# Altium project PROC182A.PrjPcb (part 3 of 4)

## Sheet PROC182A_MUX_CAN_FD.SchDoc: ANALOG MUX AND CAN FD_B
size 431 x 279 mm; Date: Not shown in title block; ApprovedBy: Not shown in title block; CheckedBy: Not shown in title block; Author: Not shown in title block; CompanyName: Not shown in title block; DrawnBy: Mistral; Engineer: Not shown in title block; Organization: Not shown in title block; Address1: Not shown in title block; Address2: Not shown in title block; Address3: Not shown in title block; Address4: Not shown in title block; DocumentNumber: 10; Revision: Use project parameter SCH_Rev; SheetNumber: 12; SheetTotal: 17; PageSetup: Record=PageOptions¦CenterHorizontal=True¦CenterVertical=True¦PrintScale=1.00¦XCorrection=1.00¦YCorrection=1.00¦PrintKind=0¦BorderSize=5000000¦LeftOffset=0¦BottomOffset=0¦Orientation=2¦PaperLength=1000¦PaperWidth=1000¦Scale=100¦PaperSource=15¦PrintQuality=600¦MediaType=1¦DitherType=10¦PaperKind=Letter¦PrintScaleMode=1
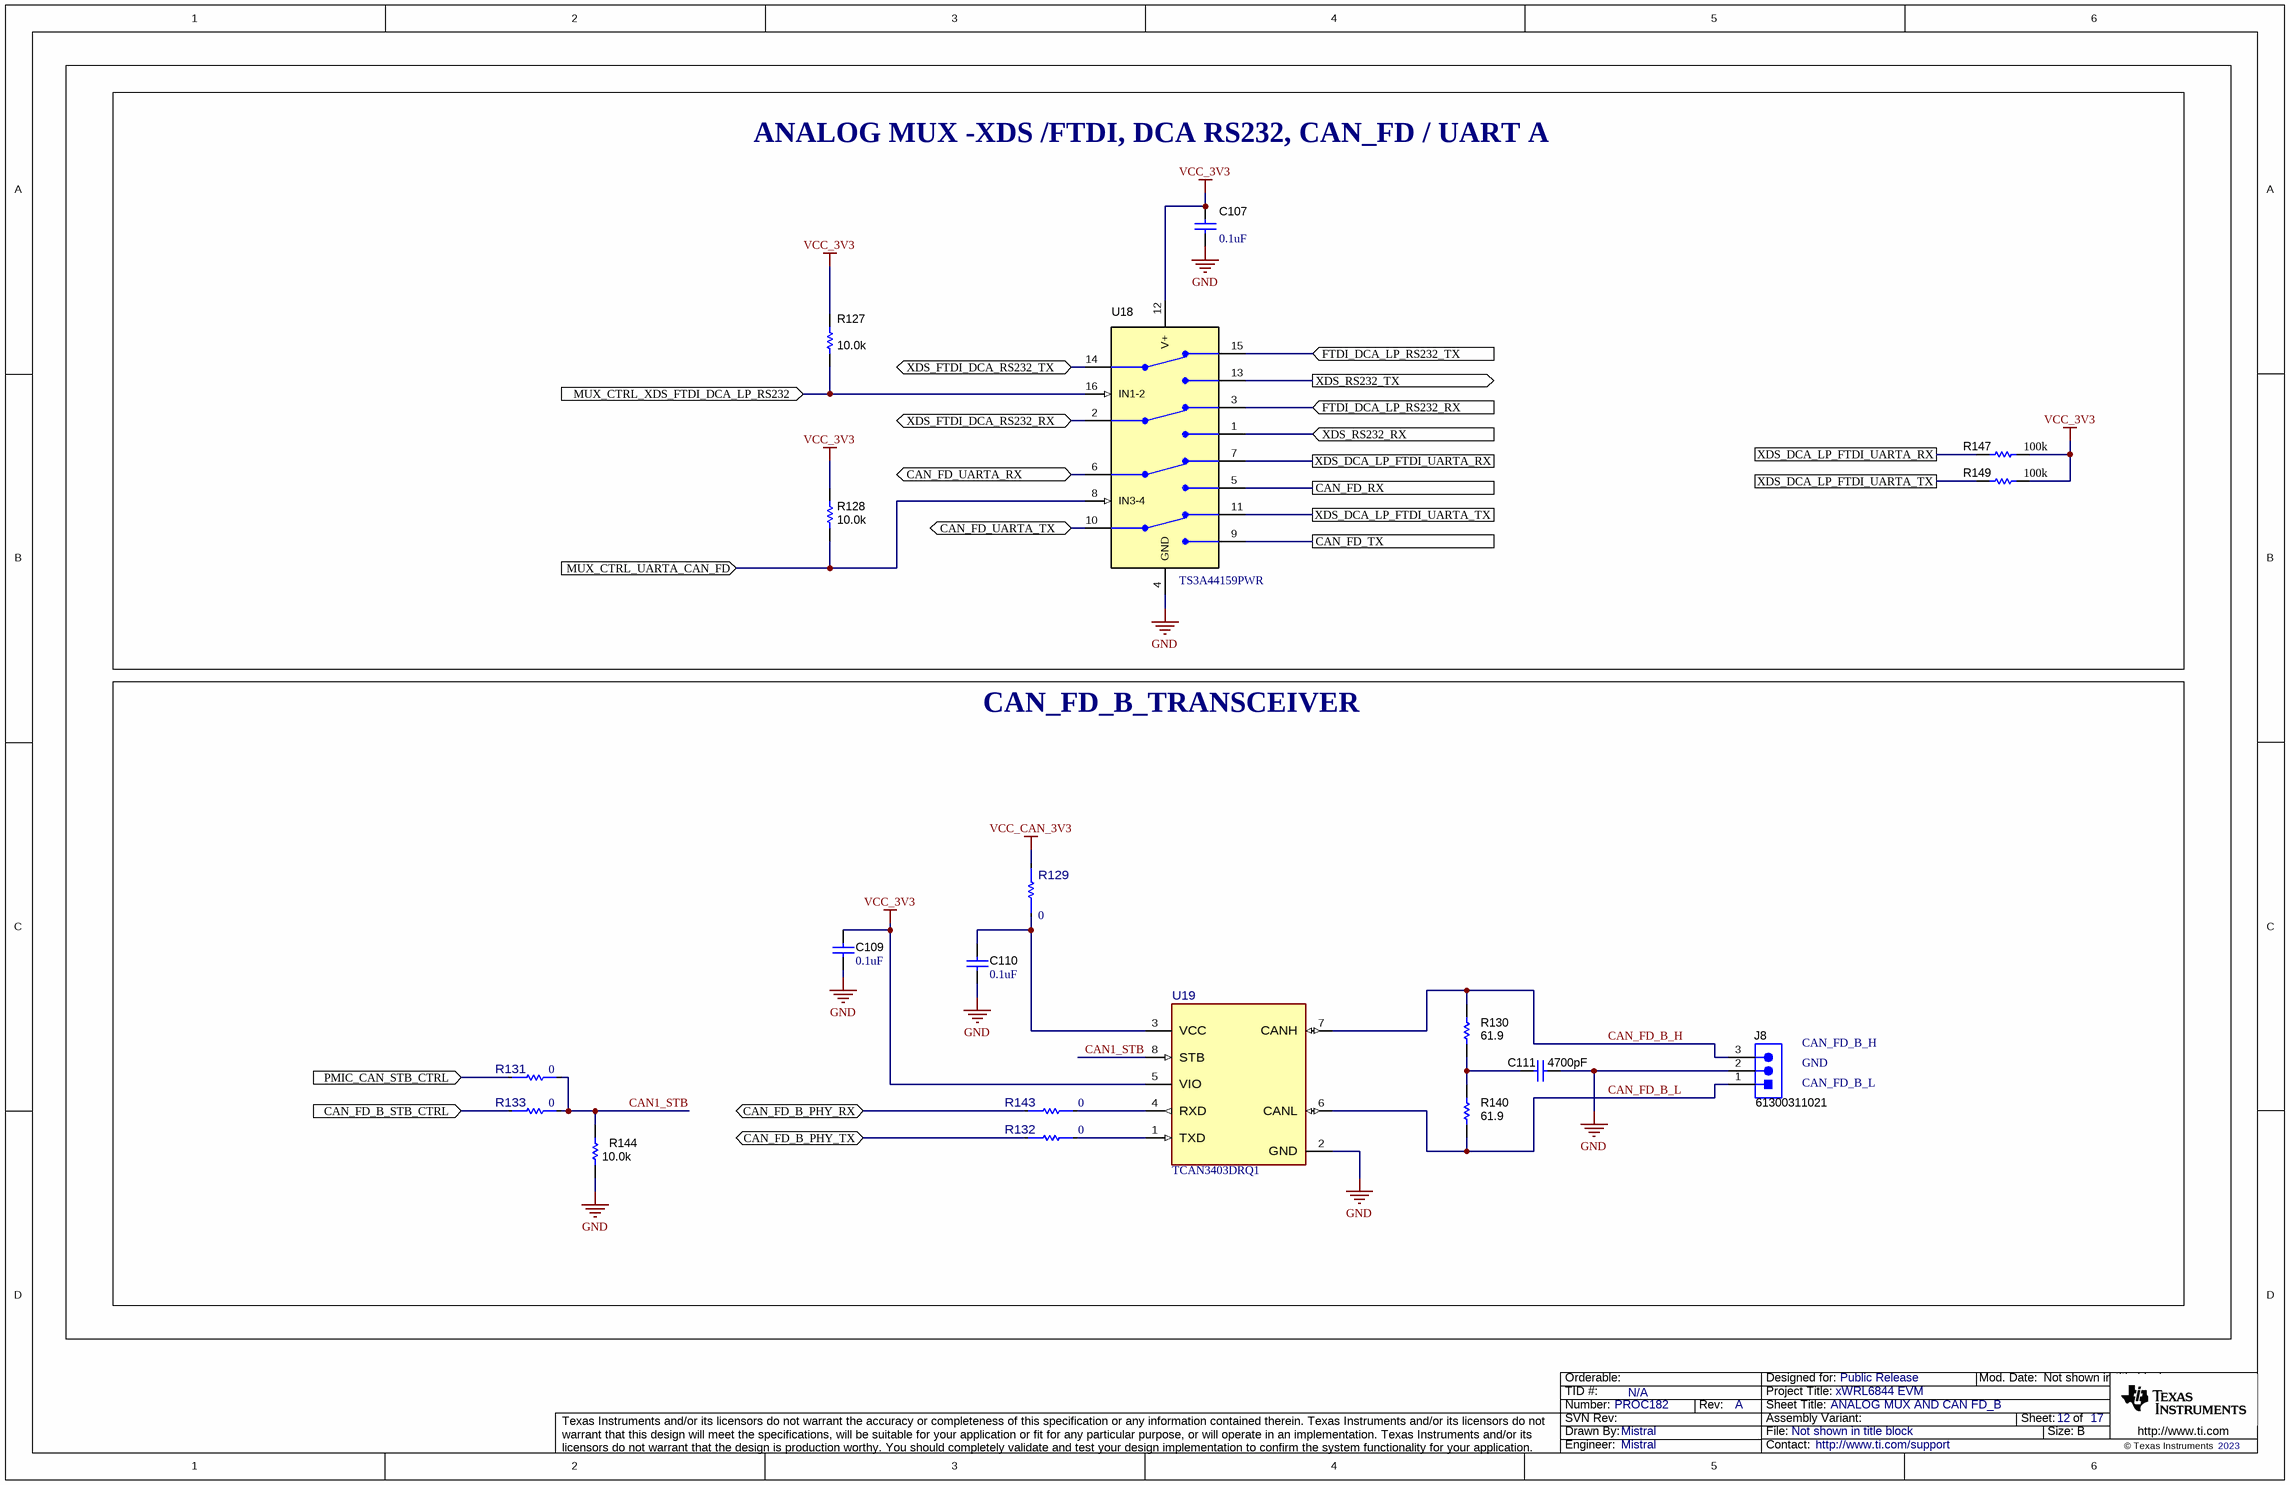
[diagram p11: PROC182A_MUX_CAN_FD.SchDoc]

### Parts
C107  ValueDisplayed: 0.1uF  [0402]  (hidden comment: GCM155R71H104KE02D)
C109  ValueDisplayed: 0.1uF  [0402]  (hidden comment: GCM155R71H104KE02D)
C110  ValueDisplayed: 0.1uF  [0402]  (hidden comment: GCM155R71H104KE02D)
C111  ValueDisplayed: 4700pF  [0402L]  (hidden comment: GCM155R71H472KA37D)
J8  61300311021  [Wurth_61300311021]
R127  ValueDisplayed: 10.0k  [0402L]  (hidden comment: CRCW040210K0FKED)
R128  ValueDisplayed: 10.0k  [0402L]  (hidden comment: CRCW040210K0FKED)
R129  value 0  [FP-ERJ-2GE0R00X_0402-MFG]  (hidden comment: ERJ-2GE0R00X)
R130  ValueDisplayed: 61.9  [0402L]  (hidden comment: CRCW040261R9FKED)
R131  value 0  [FP-ERJ-2GE0R00X_0402-MFG]  (hidden comment: ERJ-2GE0R00X)
R132  value 0  [FP-ERJ-2GE0R00X_0402-MFG]  (hidden comment: ERJ-2GE0R00X)
R133  value 0  [FP-ERJ-2GE0R00X_0402-MFG]  (hidden comment: ERJ-2GE0R00X)
R140  ValueDisplayed: 61.9  [0402L]  (hidden comment: CRCW040261R9FKED)
R143  value 0  [FP-ERJ-2GE0R00X_0402-MFG]  (hidden comment: ERJ-2GE0R00X)
R144  ValueDisplayed: 10.0k  [0402L]  (hidden comment: CRCW040210K0FKED)
R147  ValueDisplayed: 100k  [0402L]  (hidden comment: CRCW0402100KFKED)
R149  ValueDisplayed: 100k  [0402L]  (hidden comment: CRCW0402100KFKED)
U18  TS3A44159PWR  [PW0016A_N]
U19  TCAN3403DRQ1  [D0008B-MFG]

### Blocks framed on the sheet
ANALOG MUX -XDS /FTDI, DCA RS232, CAN_FD / UART A: C107 R127 R128 R147 R149 U18
CAN_FD_B_TRANSCEIVER: C109-C111 J8 R129-R133 R140 R143 R144 U19

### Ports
CAN_FD_B_PHY_RX (bidir), CAN_FD_B_PHY_TX (bidir), CAN_FD_B_STB_CTRL (in), CAN_FD_RX, CAN_FD_TX, CAN_FD_UARTA_RX (bidir), CAN_FD_UARTA_TX (bidir), FTDI_DCA_LP_RS232_RX (in), FTDI_DCA_LP_RS232_TX (in), MUX_CTRL_UARTA_CAN_FD (in), MUX_CTRL_XDS_FTDI_DCA_LP_RS232 (in), PMIC_CAN_STB_CTRL (in), XDS_DCA_LP_FTDI_UARTA_RX, XDS_DCA_LP_FTDI_UARTA_TX, XDS_FTDI_DCA_RS232_RX (bidir), XDS_FTDI_DCA_RS232_TX (bidir), XDS_RS232_RX (in), XDS_RS232_TX (out)

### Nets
GND: C107.2 C109.1 C110.1 C111.1 J8.2 R144.1 U18.4(GND) U19.2(GND)
VCC_3V3: C107.1 C109.2 R127.2 R128.2 R147.1 R149.1 U18.12(V+) U19.5(VIO)
VCC_CAN_3V3: R129.2
CAN1_STB: R131.2 R133.2 R144.2 U19.8(STB)
CAN_FD_B_H: J8.3 R130.2 U19.7(CANH)
CAN_FD_B_L: J8.1 R140.1 U19.6(CANL)
CAN_FD_B_PHY_RX: R143.1 ; port CAN_FD_B_PHY_RX
CAN_FD_B_PHY_TX: R132.1 ; port CAN_FD_B_PHY_TX
CAN_FD_B_STB_CTRL: R133.1 ; port CAN_FD_B_STB_CTRL
CAN_FD_RX: U18.5(NO3) ; port CAN_FD_RX
CAN_FD_TX: U18.9(NO4) ; port CAN_FD_TX
CAN_FD_UARTA_RX: U18.6(COM3) ; port CAN_FD_UARTA_RX
CAN_FD_UARTA_TX: U18.10(COM4) ; port CAN_FD_UARTA_TX
FTDI_DCA_LP_RS232_RX: U18.3(NC2) ; port FTDI_DCA_LP_RS232_RX
FTDI_DCA_LP_RS232_TX: U18.15(NC1) ; port FTDI_DCA_LP_RS232_TX
MUX_CTRL_UARTA_CAN_FD: R128.1 U18.8(IN3-4) ; port MUX_CTRL_UARTA_CAN_FD
MUX_CTRL_XDS_FTDI_DCA_LP_RS232: R127.1 U18.16(IN1-2) ; port MUX_CTRL_XDS_FTDI_DCA_LP_RS232
PMIC_CAN_STB_CTRL: R131.1 ; port PMIC_CAN_STB_CTRL
XDS_DCA_LP_FTDI_UARTA_RX: R147.2 U18.7(NC3) ; port XDS_DCA_LP_FTDI_UARTA_RX
XDS_DCA_LP_FTDI_UARTA_TX: R149.2 U18.11(NC4) ; port XDS_DCA_LP_FTDI_UARTA_TX
XDS_FTDI_DCA_RS232_RX: U18.2(COM2) ; port XDS_FTDI_DCA_RS232_RX
XDS_FTDI_DCA_RS232_TX: U18.14(COM1) ; port XDS_FTDI_DCA_RS232_TX
XDS_RS232_RX: U18.1(NO2) ; port XDS_RS232_RX
XDS_RS232_TX: U18.13(NO1) ; port XDS_RS232_TX
NetC110_2: C110.2 R129.1 U19.3(VCC)
NetC111_2: C111.2 R130.1 R140.2
NetR132_2: R132.2 U19.1(TXD)
NetR143_2: R143.2 U19.4(RXD)

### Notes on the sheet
- (near J8) CAN_FD_B_H
- (near J8) GND
- (near J8) CAN_FD_B_L

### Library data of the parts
C107 C109 C110 = CMP-0006356-2: CAP, CERM, 0.1 uF, 50 V, +/- 10%, X7R, AEC-Q200 Grade 1, 0402; Manufacturer: MuRata; TaMin_C: -55°C; Polarized: N; SizeAreaWB_mm2: 3; U/M: EA; Value: 0.1uF; TaMax_C: 125°C; SizeZ_mm: 0.6; SizeX_mm: 1; SizeY_mm: 0.5; Value2: 50V; AEC Qualified: Y; Cap_F: 100nF; AEC Category: Q200; Value1: Unknown
C111 = CMP-0006361-2: CAP, CERM, 4700 pF, 50 V, +/- 10%, X7R, AEC-Q200 Grade 1, 0402; Manufacturer: MuRata; TaMin_C: -55°C; Polarized: N; SizeAreaWB_mm2: 3; Value1: Unknown; U/M: EA; Value: 4700pF; TaMax_C: 125°C; SizeZ_mm: 0.6; SizeX_mm: 1; SizeY_mm: 0.5; Cap_Case: 0402; Value2: 50V; AEC Qualified: Y; Cap_F: 4.7nF; AEC Category: Q200
J8 = CMP-0054795-1: Header, 2.54 mm, 3x1, Gold, R/A, TH; Manufacturer: Wurth Elektronik; CNHeader: TRUE; Shrouded: N; Gender: Male; Row_Count: 1; Pitch_mm: 2.54; CT: FALSE
R127 R128 R144 = CMP-0025958-3: RES, 10.0 k, 1%, 0.063 W, AEC-Q200 Grade 0, 0402; Manufacturer: Vishay-Dale; Power_W: 63mW; TempCo: 100 ppm/C; Value_Code: 10k0; Value: 10.0k; EIA_Code: E96; Res_ohm: 10k; SizeX_mm: 1; SizeY_mm: 0.5; SizeZ_mm: 0.6; Value2: 0.063W; AEC Qualified: Y; VDC_V: 50V; AEC Category: Q200; AEC Grade: 0
R129 R131-R133 R143 = CMP-0002710-1: 0 Ohms Jumper Chip Resistor 0402 (1005 Metric) Automotive AEC-Q200 Thick Film; Manufacturer: Panasonic; SizeZ_mm: 0.4mm; AEC Qualified: Yes; AEC Grade: Grade 0; Power: 100mW
R130 R140 = CMP-0026491-2: RES, 61.9, 1%, 0.063 W, AEC-Q200 Grade 0, 0402; Manufacturer: Vishay-Dale; Power_W: 63mW; TempCo: 100 ppm/C; Value_Code: 61R9; Value: 61.9; EIA_Code: E96; SizeX_mm: 1; SizeY_mm: 0.5; SizeZ_mm: 0.6; Value2: 0.063W; AEC Qualified: Y; VDC_V: 50V; AEC Category: Q200; AEC Grade: 0
R147 R149 = CMP-0025950-3: RES, 100 k, 1%, 0.063 W, AEC-Q200 Grade 0, 0402; Manufacturer: Vishay-Dale; Power_W: 63mW; TempCo: 100 ppm/C; Value: 100k; EIA_Code: E96; SizeX_mm: 1; SizeY_mm: 0.5; SizeZ_mm: 0.6; Value2: 0.063W; AEC Qualified: Y; VDC_V: 50V; AEC Category: Q200; AEC Grade: 0
U18 = CMP-0067412-1: 0.45-Ohm Quad SPDT Analog Switch Quad-Channel 2:1 Multiplexer/Demultiplexer with Two Controls, PW0016A (TSSOP-16); Alternate Manufacturer: Texas Instruments; SizeAreaWB_mm2: 58.8; U/M: EA; SizeZ_mm: 1.2; SizeX_mm: 6.4; SizeY_mm: 5.0; SizeArea_mm2: 32.0; CompType: IC
U19 = CMP-0121020-1: Dual, Simultaneous-Sampling, 16-Bit, 5 MSPS SAR ADCs; Manufacturer: Texas Instruments; SizeZ_mm: 1.75mm; AEC Qualified: Yes; AEC Grade: Grade 1; Interface: CAN; Max Supply Voltage: 3.6V; Min Supply Voltage: 1.7V; Standoff Height: 0.11mm

## Sheet PROC182A_CAN_LIN_PHY_Interface.SchDoc: CAN_LIN_PHY_INTERFACE
size 431 x 279 mm; Date: Not shown in title block; ApprovedBy: Not shown in title block; CheckedBy: Not shown in title block; Author: Not shown in title block; CompanyName: Not shown in title block; DrawnBy: Mistral; Engineer: Not shown in title block; Organization: Not shown in title block; Address1: Not shown in title block; Address2: Not shown in title block; Address3: Not shown in title block; Address4: Not shown in title block; DocumentNumber: 13; Revision: Use project parameter SCH_Rev; SheetNumber: 13; SheetTotal: 17; PageSetup: Record=PageOptions¦CenterHorizontal=True¦CenterVertical=True¦PrintScale=1.00¦XCorrection=1.00¦YCorrection=1.00¦PrintKind=0¦BorderSize=5000000¦LeftOffset=0¦BottomOffset=0¦Orientation=2¦PaperLength=1000¦PaperWidth=1000¦Scale=100¦PaperSource=15¦PrintQuality=600¦MediaType=1¦DitherType=10¦PaperKind=Letter¦PrintScaleMode=1
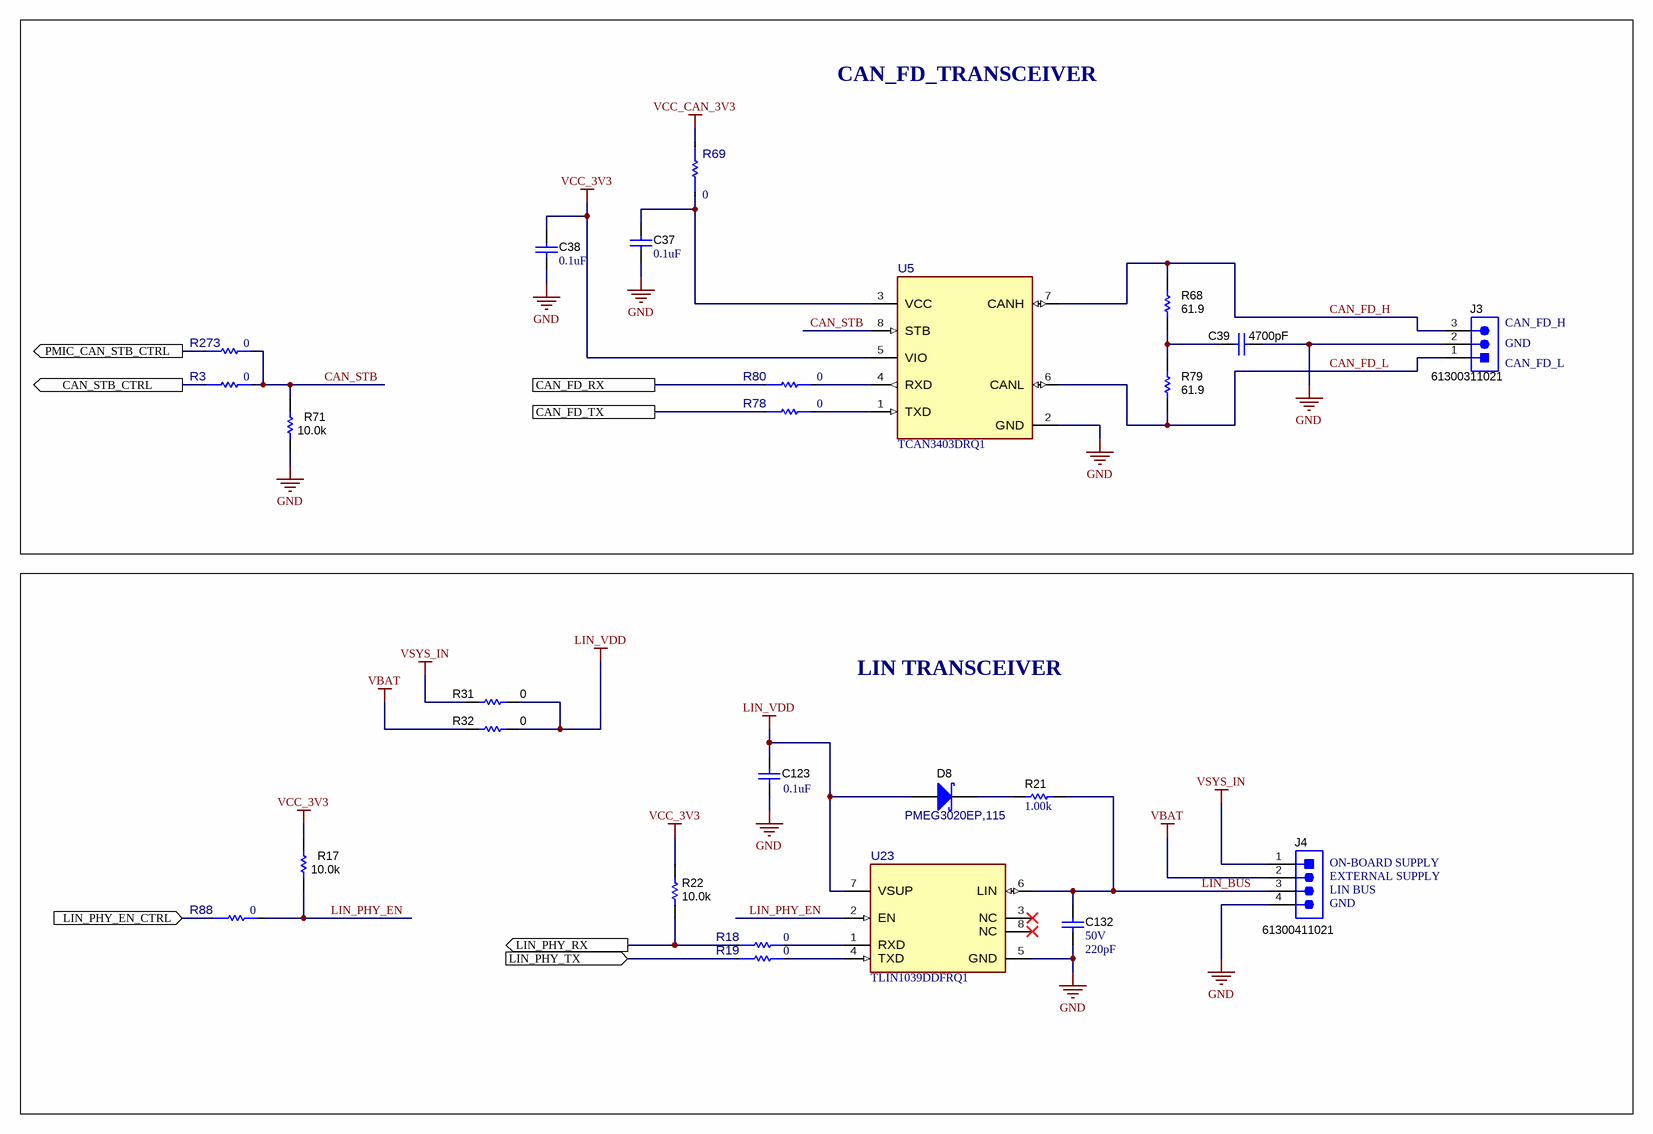
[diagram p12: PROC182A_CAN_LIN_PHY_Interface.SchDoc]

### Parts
C37  ValueDisplayed: 0.1uF  [0402]  (hidden comment: GCM155R71H104KE02D)
C38  ValueDisplayed: 0.1uF  [0402]  (hidden comment: GCM155R71H104KE02D)
C39  ValueDisplayed: 4700pF  [0402L]  (hidden comment: GCM155R71H472KA37D)
C123  ValueDisplayed: 0.1uF  [0402]  (hidden comment: GCM155R71H104KE02D)
C132  VDC_V: 50V  ValueDisplayed: 220pF  [0402]  (hidden comment: 885012005063)
D8  PMEG3020EP,115  [SOD-128]
J3  61300311021  [Wurth_61300311021]
J4  61300411021  [Wurth_61300411021]
R3  value 0  [FP-ERJ-2GE0R00X_0402-MFG]  (hidden comment: ERJ-2GE0R00X)
R17  ValueDisplayed: 10.0k  [0402L]  (hidden comment: CRCW040210K0FKED)
R18  value 0  [FP-ERJ-2GE0R00X_0402-MFG]  (hidden comment: ERJ-2GE0R00X)
R19  value 0  [FP-ERJ-2GE0R00X_0402-MFG]  (hidden comment: ERJ-2GE0R00X)
R21  ValueDisplayed: 1.00k  [0402]  (hidden comment: ERJ-2RKF1001X)
R22  ValueDisplayed: 10.0k  [0402L]  (hidden comment: CRCW040210K0FKED)
R31  ValueDisplayed: 0  [0603]  (hidden comment: MCT06030Z0000ZP500)
R32  ValueDisplayed: 0  [0603]  (hidden comment: MCT06030Z0000ZP500)
R68  ValueDisplayed: 61.9  [0402L]  (hidden comment: CRCW040261R9FKED)
R69  value 0  [FP-ERJ-2GE0R00X_0402-MFG]  (hidden comment: ERJ-2GE0R00X)
R71  ValueDisplayed: 10.0k  [0402L]  (hidden comment: CRCW040210K0FKED)
R78  value 0  [FP-ERJ-2GE0R00X_0402-MFG]  (hidden comment: ERJ-2GE0R00X)
R79  ValueDisplayed: 61.9  [0402L]  (hidden comment: CRCW040261R9FKED)
R80  value 0  [FP-ERJ-2GE0R00X_0402-MFG]  (hidden comment: ERJ-2GE0R00X)
R88  value 0  [FP-ERJ-2GE0R00X_0402-MFG]  (hidden comment: ERJ-2GE0R00X)
R273  value 0  [FP-ERJ-2GE0R00X_0402-MFG]  (hidden comment: ERJ-2GE0R00X)
U5  TCAN3403DRQ1  [D0008B-MFG]
U23  TLIN1039DDFRQ1  [DDF0008A-MFG]

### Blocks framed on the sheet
CAN_FD_TRANSCEIVER: C37-C39 J3 R3 R68 R69 R71 R78-R80 R273 U5
LIN TRANSCEIVER: C123 C132 D8 J4 R17-R19 R21 R22 R31 R32 R88 U23

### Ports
CAN_FD_RX, CAN_FD_TX, CAN_STB_CTRL (out), LIN_PHY_EN_CTRL (in), LIN_PHY_RX (out), LIN_PHY_TX (in), PMIC_CAN_STB_CTRL (out)

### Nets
GND: C37.1 C38.1 C39.1 C123.2 C132.2 J3.2 J4.4 R71.1 U5.2(GND) U23.5(GND)
LIN_VDD: C123.1 D8.2(A) R31.2 R32.2 U23.7(VSUP)
VBAT: J4.2 R32.1
VCC_3V3: C38.2 R17.2 R22.2 U5.5(VIO)
VCC_CAN_3V3: R69.2
VSYS_IN: J4.1 R31.1
CAN_FD_H: J3.3 R68.2 U5.7(CANH)
CAN_FD_L: J3.1 R79.1 U5.6(CANL)
CAN_FD_RX: R80.1 ; port CAN_FD_RX
CAN_FD_TX: R78.1 ; port CAN_FD_TX
CAN_STB: R3.2 R71.2 R273.2 U5.8(STB)
CAN_STB_CTRL: R3.1 ; port CAN_STB_CTRL
LIN_BUS: C132.1 J4.3 R21.1 U23.6(LIN)
LIN_PHY_EN: R17.1 R88.2 U23.2(EN)
LIN_PHY_EN_CTRL: R88.1 ; port LIN_PHY_EN_CTRL
LIN_PHY_RX: R18.1 R22.1 ; port LIN_PHY_RX
LIN_PHY_TX: R19.1 ; port LIN_PHY_TX
PMIC_CAN_STB_CTRL: R273.1 ; port PMIC_CAN_STB_CTRL
NetC37_2: C37.2 R69.1 U5.3(VCC)
NetC39_2: C39.2 R68.1 R79.2
NetD8_1: D8.1(K) R21.2
NetR18_2: R18.2 U23.1(RXD)
NetR19_2: R19.2 U23.4(TXD)
NetR78_2: R78.2 U5.1(TXD)
NetR80_2: R80.2 U5.4(RXD)

Not connected (* = marked no-connect by the designer): U23 3(NC)* 8(NC)*

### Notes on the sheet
- (near J3) CAN_FD_H
- (near J3) GND
- (near J3) CAN_FD_L
- (near J4) ON-BOARD SUPPLY
- (near J4) EXTERNAL SUPPLY
- (near J4) LIN BUS
- (near J4) GND

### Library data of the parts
C37 C38 = CMP-0006356-2: as C107 on sheet PROC182A_MUX_CAN_FD
C39 = CMP-0006361-2: as C111 on sheet PROC182A_MUX_CAN_FD
C123 = CMP-0006356-2: CAP, CERM, 0.1 uF, 50 V, +/- 10%, X7R, AEC-Q200 Grade 1, 0402; Manufacturer: MuRata; TaMin_C: -55°C; Polarized: N; SizeAreaWB_mm2: 3; Value1: Unknown; U/M: EA; Value: 0.1uF; TaMax_C: 125°C; SizeZ_mm: 0.6; SizeX_mm: 1; SizeY_mm: 0.5; Value2: 50V; AEC Qualified: Y; Cap_F: 100nF; AEC Category: Q200
C132 = CMP-0006218-2: CAP, CERM, 220 pF, 50 V, +/- 5%, C0G/NP0, 0402; Manufacturer: Wurth Elektronik; TaMin_C: -55°C; Polarized: N; SizeAreaWB_mm2: 3; Value1: Unknown; U/M: EA; Value: 220pF; TaMax_C: 125°C; SizeZ_mm: 0.6; SizeX_mm: 1; SizeY_mm: 0.5; AEC Category: Q200
D8 = CMP-0078758-2: Diode, Schottky, 30 V, 2 A, AEC-Q101, SOD-128; Manufacturer: Nexperia; Value2: 0.36V; SizeAreaWB_mm2: 19.6; Io_A: 2A; Value: 30V; AEC Qualified: Y; TJmax_C: 150°C; SizeX_mm: 4.6; AEC Category: Q101; SizeY_mm: 2.5; SizeArea_mm2: 11.5; Vf_V: 3.6dV; SizeZ_mm: 1.1
J3 = CMP-0054795-1: as J8 on sheet PROC182A_MUX_CAN_FD
J4 = CMP-0054797-1: Header, 2.54 mm, 4x1, Gold, R/A, TH; Manufacturer: Wurth Elektronik; CNHeader: TRUE; Shrouded: N; Gender: Male; Row_Count: 1; Pitch_mm: 2.54; CT: FALSE
R3 R18 R19 R69 R78 R80 R88 R273 = CMP-0002710-1: as R129 on sheet PROC182A_MUX_CAN_FD
R17 R22 R71 = CMP-0025958-3: as R127 on sheet PROC182A_MUX_CAN_FD
R21 = CMP-0026657-1: RES, 1.00 k, 1%, 0.1 W, 0402; Manufacturer: Panasonic; Power_W: 100mW; TempCo: 100 ppm/C; Value_Code: 1k00; Value: 1.00k; EIA_Code: E96; Res_ohm: 1k; SizeX_mm: 1; SizeY_mm: 0.5; SizeZ_mm: 0.6; Value2: 0.1W; VDC_V: 50V; AEC Category: Q200; U/M: EA
R31 R32 = CMP-0025884-3: RES, 0, 5%, 0.125 W, 0603; Manufacturer: Vishay/Beyschlag; Power_W: 125mW; TempCo: ppm/C; Value_Code: 0000; U/M: EA; Value: 0; EIA_Code: E24; SizeX_mm: 1.6; SizeY_mm: 0.8; SizeZ_mm: 1; Value2: 0.125W; SizeArea_mm2: 1.28; CompType: Resistor; AEC Qualified: N; AEC Category: Q200; INSTALATION: DNP
R68 R79 = CMP-0026491-2: as R130 on sheet PROC182A_MUX_CAN_FD
U5 = CMP-0121020-1: as U19 on sheet PROC182A_MUX_CAN_FD
U23 = CMP-0090433-1: Local Interconnect Network (LIN) Transceiver with Dominant State Timeout; Manufacturer: Texas Instruments; Max Supply Voltage: 36V; SizeZ_mm: 1.1mm; Min Supply Voltage: 4.5V; Standoff Height: 0mm; Nominal Supply Current: 0.3-1.2mA; AEC Grade: Grade 0; TJmax_C: +150°C; Interface: UART,LIN,SCI; AEC Qualified: Yes

## Sheet PROC182A_FTDI.SchDoc: FTDI_USB to SPI/12C/UART_Converter
size 431 x 279 mm; Date: Not shown in title block; ApprovedBy: Not shown in title block; CheckedBy: Not shown in title block; Author: Not shown in title block; CompanyName: Not shown in title block; DrawnBy: Mistral; Engineer: Not shown in title block; Organization: Not shown in title block; Address1: Not shown in title block; Address2: Not shown in title block; Address3: Not shown in title block; Address4: Not shown in title block; DocumentNumber: 14; Revision: Use project parameter SCH_Rev; SheetNumber: 14; SheetTotal: 17; PageSetup: Record=PageOptions¦CenterHorizontal=True¦CenterVertical=True¦PrintScale=1.00¦XCorrection=1.00¦YCorrection=1.00¦PrintKind=0¦BorderSize=5000000¦LeftOffset=0¦BottomOffset=0¦Orientation=2¦PaperLength=1000¦PaperWidth=1000¦Scale=100¦PaperSource=15¦PrintQuality=600¦MediaType=1¦DitherType=10¦PaperKind=Letter¦PrintScaleMode=1
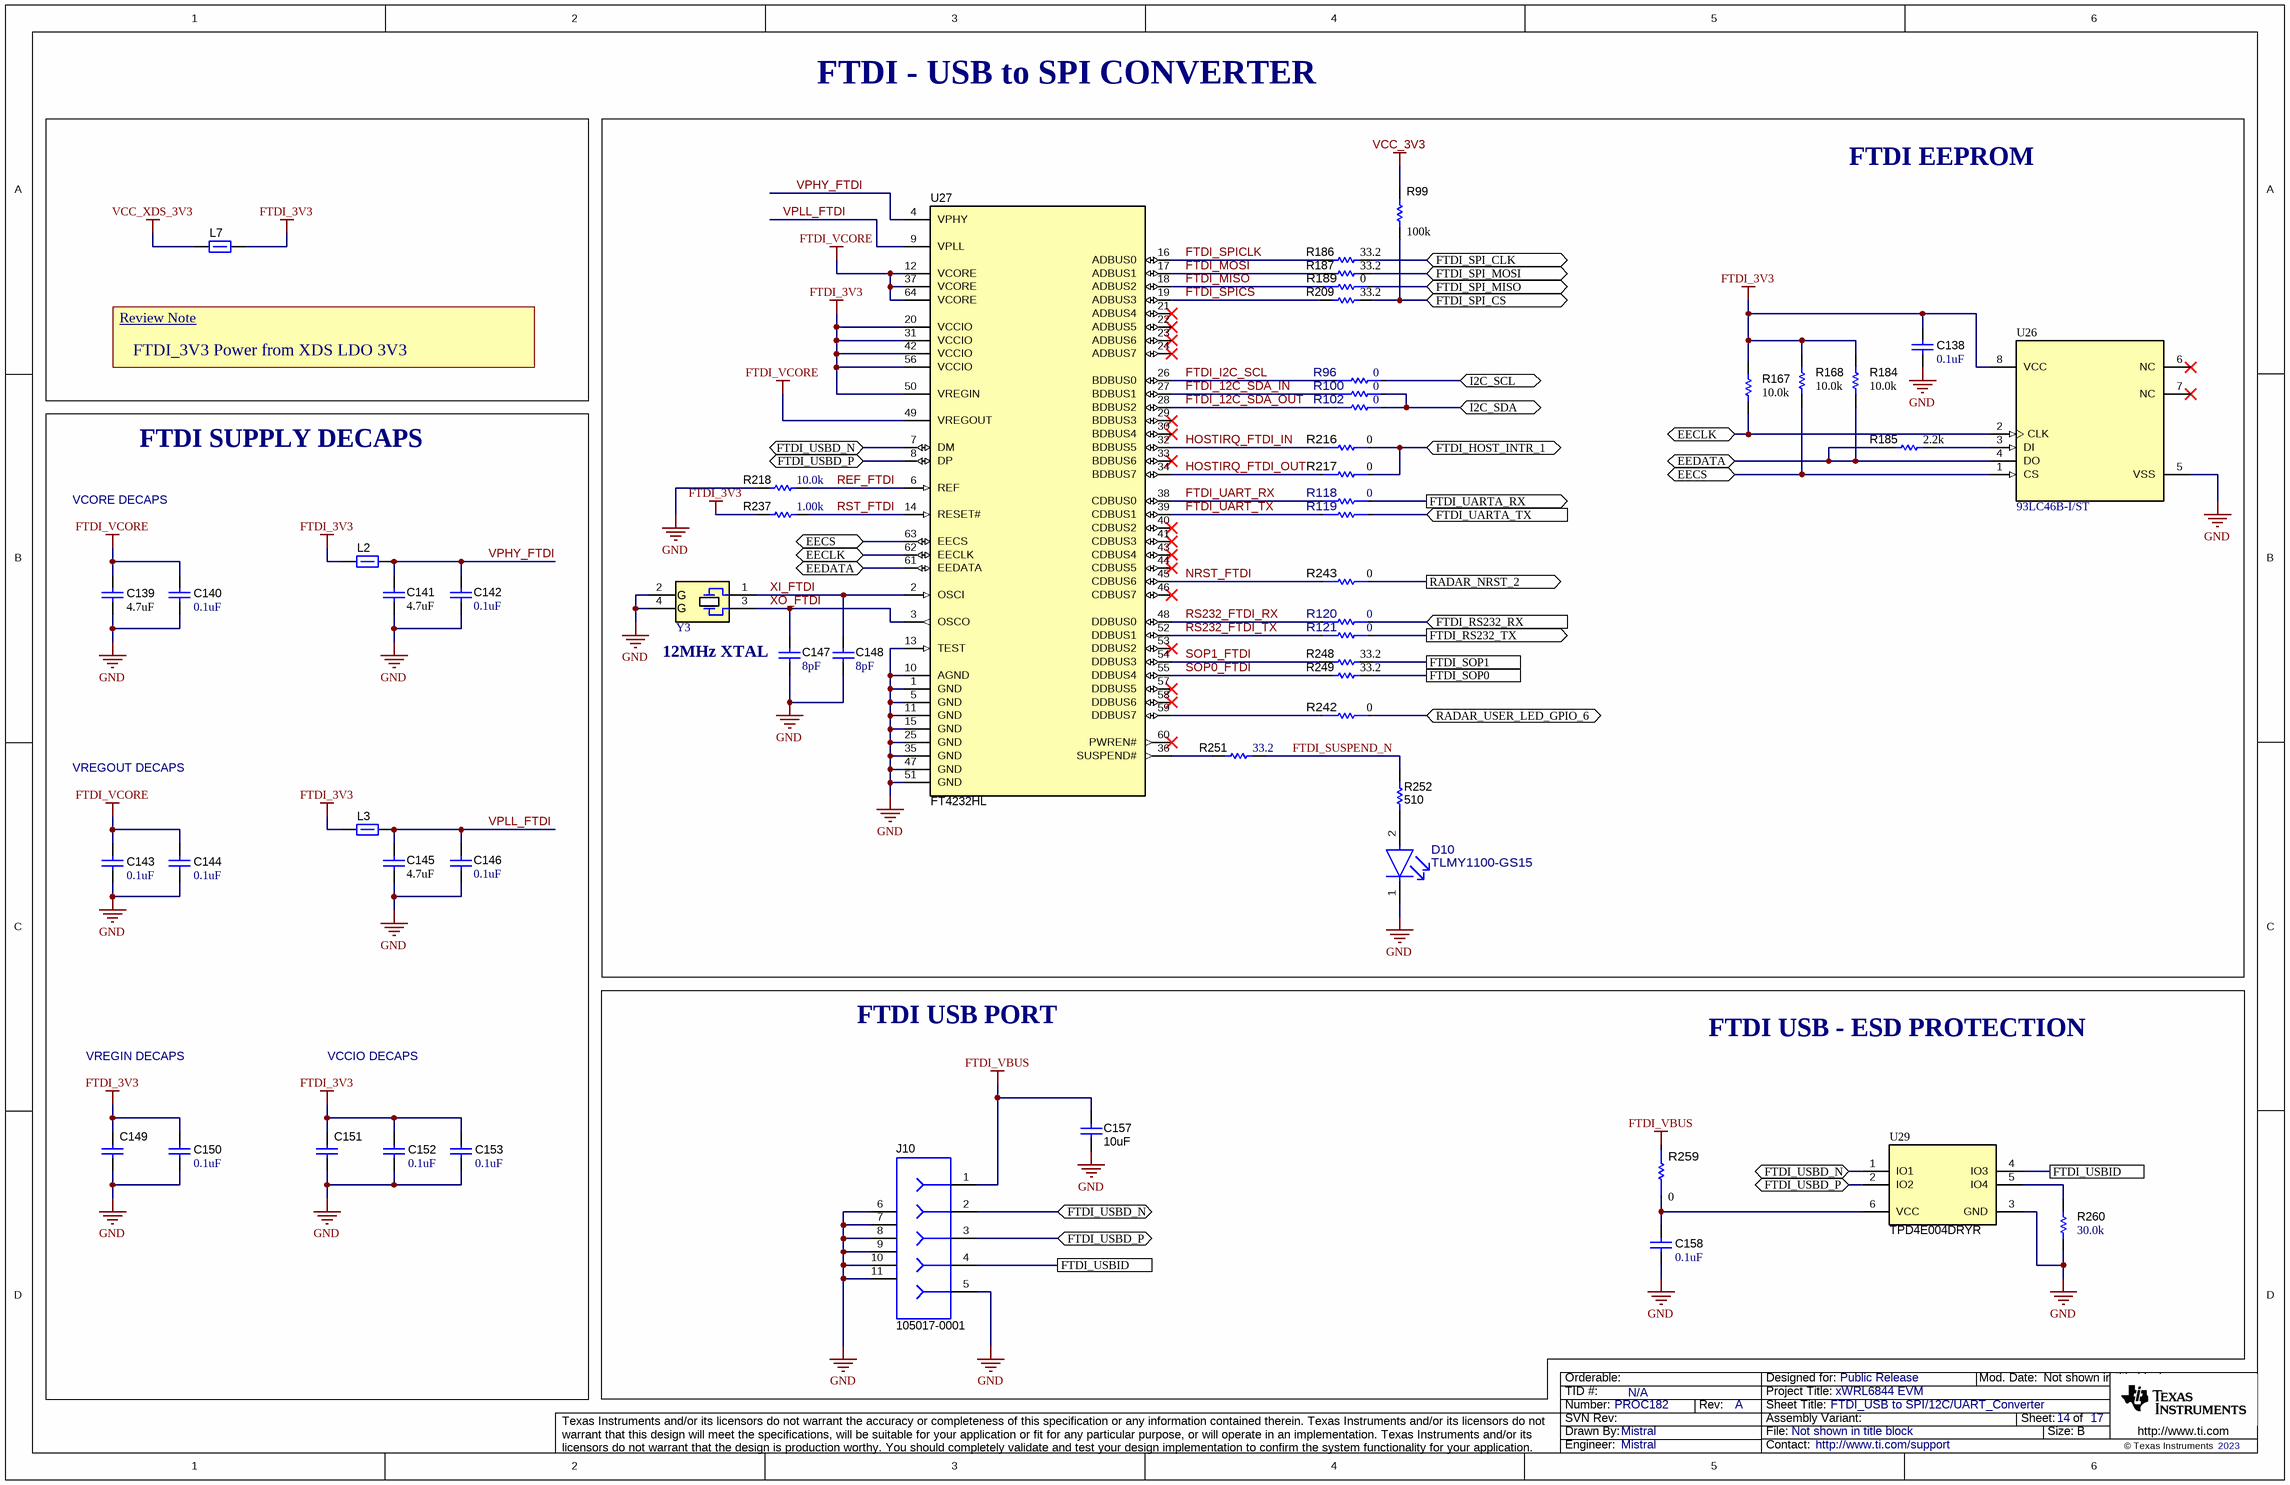
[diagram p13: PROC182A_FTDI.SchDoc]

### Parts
C138  ValueDisplayed: 0.1uF  [0402]  (hidden comment: GCM155R71H104KE02D)
C139  ValueDisplayed: 4.7uF  [0603L]  (hidden comment: C1608X7S1A475K080AC)
C140  ValueDisplayed: 0.1uF  [0402]  (hidden comment: GCM155R71H104KE02D)
C141  ValueDisplayed: 4.7uF  [0603L]  (hidden comment: C1608X7S1A475K080AC)
C142  ValueDisplayed: 0.1uF  [0402]  (hidden comment: GCM155R71H104KE02D)
C143  ValueDisplayed: 0.1uF  [0402]  (hidden comment: GCM155R71H104KE02D)
C144  ValueDisplayed: 0.1uF  [0402]  (hidden comment: GCM155R71H104KE02D)
C145  ValueDisplayed: 4.7uF  [0603L]  (hidden comment: C1608X7S1A475K080AC)
C146  ValueDisplayed: 0.1uF  [0402]  (hidden comment: GCM155R71H104KE02D)
C147  Cap_F: 8pF  [0402L]  (hidden comment: GCM1555C1H8R0DA16D)
C148  Cap_F: 8pF  [0402L]  (hidden comment: GCM1555C1H8R0DA16D)
C149  CL10B105KA8NNNC  [0603]  (value not drawn)
C150  ValueDisplayed: 0.1uF  [0402]  (hidden comment: GCM155R71H104KE02D)
C151  CL10B105KA8NNNC  [0603]  (value not drawn)
C152  ValueDisplayed: 0.1uF  [0402]  (hidden comment: GCM155R71H104KE02D)
C153  ValueDisplayed: 0.1uF  [0402]  (hidden comment: GCM155R71H104KE02D)
C157  ValueDisplayed: 10uF  [0603S]  (hidden comment: GRT188R61A106KE13D)
C158  ValueDisplayed: 0.1uF  [0402]  (hidden comment: GCM155R71H104KE02D)
D10  TLMY1100-GS15  [FP-TLMY1100-GS15_0603-MFG]
J10  105017-0001  [CONN_105017-0001]
L2  BLM15HG601SN1D  [0402L]  (value not drawn)
L3  BLM15HG601SN1D  [0402L]  (value not drawn)
L7  BLM15HG601SN1D  [0402L]  (value not drawn)
R96  value 0  [FP-ERJ-2GE0R00X_0402-MFG]  (hidden comment: ERJ-2GE0R00X)
R99  ValueDisplayed: 100k  [0402]  (hidden comment: CRCW0402100KFKED)
R100  value 0  [FP-ERJ-2GE0R00X_0402-MFG]  (hidden comment: ERJ-2GE0R00X)
R102  value 0  [FP-ERJ-2GE0R00X_0402-MFG]  (hidden comment: ERJ-2GE0R00X)
R118  value 0  [FP-ERJ-2GE0R00X_0402-MFG]  (hidden comment: ERJ-2GE0R00X)
R119  ERJ-2GE0R00X  [FP-ERJ-2GE0R00X_0402-MFG]  (value not drawn)
R120  value 0  [FP-ERJ-2GE0R00X_0402-MFG]  (hidden comment: ERJ-2GE0R00X)
R121  value 0  [FP-ERJ-2GE0R00X_0402-MFG]  (hidden comment: ERJ-2GE0R00X)
R167  ValueDisplayed: 10.0k  [0402L]  (hidden comment: CRCW040210K0FKED)
R168  ValueDisplayed: 10.0k  [0402L]  (hidden comment: CRCW040210K0FKED)
R184  ValueDisplayed: 10.0k  [0402L]  (hidden comment: CRCW040210K0FKED)
R185  ValueDisplayed: 2.2k  [0402L]  (hidden comment: CRCW04022K20JNED)
R186  ValueDisplayed: 33.2  [0402]  (hidden comment: CRCW040233R2FKED)
R187  ValueDisplayed: 33.2  [0402]  (hidden comment: CRCW040233R2FKED)
R189  value 0  [FP-ERJ-2GE0R00X_0402-MFG]  (hidden comment: ERJ-2GE0R00X)
R209  ValueDisplayed: 33.2  [0402]  (hidden comment: CRCW040233R2FKED)
R216  value 0  [FP-ERJ-2GE0R00X_0402-MFG]  (hidden comment: ERJ-2GE0R00X)
R217  value 0  [FP-ERJ-2GE0R00X_0402-MFG]  (hidden comment: ERJ-2GE0R00X)
R218  ValueDisplayed: 10.0k  [0402L]  (hidden comment: CRCW040210K0FKED)
R237  ValueDisplayed: 1.00k  [0402]  (hidden comment: ERJ-2RKF1001X)
R242  value 0  [FP-ERJ-2GE0R00X_0402-MFG]  (hidden comment: ERJ-2GE0R00X)
R243  value 0  [FP-ERJ-2GE0R00X_0402-MFG]  (hidden comment: ERJ-2GE0R00X)
R248  ValueDisplayed: 33.2  [0402]  (hidden comment: CRCW040233R2FKED)
R249  ValueDisplayed: 33.2  [0402]  (hidden comment: CRCW040233R2FKED)
R251  ValueDisplayed: 33.2  [0402]  (hidden comment: CRCW040233R2FKED)
R252  ValueDisplayed: 510  [0402L]  (hidden comment: ERJ-2GEJ511X)
R259  value 0  [FP-ERJ-2GE0R00X_0402-MFG]  (hidden comment: ERJ-2GE0R00X)
R260  ValueDisplayed: 30.0k  [0402L]  (hidden comment: CRCW040230K0FKED)
U26  93LC46B-I/ST  [TSSOP-8]
U27  FT4232HL  [LQFP64_N]
U29  TPD4E004DRYR  [DRY0006A]
Y3  NX3225SA-12.000M-STD-CRS-2  [NDK_NX3225SA]  (value not drawn)

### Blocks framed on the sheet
FTDI_3V3 Power from XDS LDO 3V3: L7
FTDI EEPROM: C138 C147 C148 D10 R96 R99 R100 R102 R118-R121 R167 R168 R184-R187 R189 R209 R216-R218 R237 R242 R243 R248 R249 R251 R252 U26 U27 Y3
FTDI SUPPLY DECAPS: C139-C146 C149-C153 L2 L3

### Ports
EECLK (bidir), EECS (bidir), EEDATA (bidir), FTDI_HOST_INTR_1 (bidir), FTDI_RS232_RX (in), FTDI_RS232_TX (out), FTDI_SOP0, FTDI_SOP1, FTDI_SPI_CLK (bidir), FTDI_SPI_CS (bidir), FTDI_SPI_MISO (bidir), FTDI_SPI_MOSI (bidir), FTDI_UARTA_RX (out), FTDI_UARTA_TX (in), FTDI_USBD_N (bidir), FTDI_USBD_P (bidir), FTDI_USBID, I2C_SCL (bidir), I2C_SDA (bidir), RADAR_NRST_2 (out), RADAR_USER_LED_GPIO_6 (bidir)

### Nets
FTDI_3V3: C138.1 C149.2 C150.1 C151.2 C152.1 C153.1 L2.1 L3.1 L7.2 R167.2 R168.2 R184.2 R237.1 U26.8(VCC) U27.20(VCCIO) U27.31(VCCIO) U27.42(VCCIO) U27.50(VREGIN) U27.56(VCCIO)
FTDI_VBUS: C157.2 J10.1 R259.2
FTDI_VCORE: C139.1 C140.1 C143.1 C144.1 U27.12(VCORE) U27.37(VCORE) U27.49(VREGOUT) U27.64(VCORE)
GND: C138.2 C139.2 C140.2 C141.2 C142.1 C143.2 C144.2 C145.2 C146.1 C147.2 C148.2 C149.1 C150.2 C151.1 C152.2 C153.2 C157.1 C158.2 D10.1(C) J10.5 J10.6 J10.7 J10.8 J10.9 J10.10 J10.11 R218.1 R260.1 U26.5(VSS) U27.1(GND) U27.5(GND) U27.10(AGND) U27.11(GND) U27.13(TEST) U27.15(GND) U27.25(GND) U27.35(GND) U27.47(GND) U27.51(GND) U29.3(GND) Y3.2(GND) Y3.4(GND)
VCC_3V3: R99.2
VCC_XDS_3V3: L7.1
EECLK: R167.1 U26.2(CLK) U27.62(EECLK) ; port EECLK
EECS: R168.1 U26.1(CS) U27.63(EECS) ; port EECS
EEDATA: R184.1 R185.1 U26.4(DO) U27.61(EEDATA) ; port EEDATA
FTDI_12C_SDA_IN: R100.1 U27.27(BDBUS1)
FTDI_12C_SDA_OUT: R102.1 U27.28(BDBUS2)
FTDI_HOST_INTR_1: R216.2 R217.2 ; port FTDI_HOST_INTR_1
FTDI_I2C_SCL: R96.1 U27.26(BDBUS0)
FTDI_MISO: R189.1 U27.18(ADBUS2)
FTDI_MOSI: R187.1 U27.17(ADBUS1)
FTDI_RS232_RX: R120.2 ; port FTDI_RS232_RX
FTDI_RS232_TX: R121.2 ; port FTDI_RS232_TX
FTDI_SOP0: R249.2 ; port FTDI_SOP0
FTDI_SOP1: R248.2 ; port FTDI_SOP1
FTDI_SPI_CLK: R186.2 ; port FTDI_SPI_CLK
FTDI_SPI_CS: R99.1 R209.2 ; port FTDI_SPI_CS
FTDI_SPI_MISO: R189.2 ; port FTDI_SPI_MISO
FTDI_SPI_MOSI: R187.2 ; port FTDI_SPI_MOSI
FTDI_SPICLK: R186.1 U27.16(ADBUS0)
FTDI_SPICS: R209.1 U27.19(ADBUS3)
FTDI_SUSPEND_N: R251.2 R252.1
FTDI_UART_RX: R118.1 U27.38(CDBUS0)
FTDI_UART_TX: R119.1 U27.39(CDBUS1)
FTDI_UARTA_RX: R118.2 ; port FTDI_UARTA_RX
FTDI_UARTA_TX: R119.2 ; port FTDI_UARTA_TX
FTDI_USBD_N: J10.2 U27.7(DM) U29.1(IO1) ; port FTDI_USBD_N
FTDI_USBD_P: J10.3 U27.8(DP) U29.2(IO2) ; port FTDI_USBD_P
FTDI_USBID: J10.4 U29.4(IO3) ; port FTDI_USBID
HOSTIRQ_FTDI_IN: R216.1 U27.32(BDBUS5)
HOSTIRQ_FTDI_OUT: R217.1 U27.34(BDBUS7)
I2C_SCL: R96.2 ; port I2C_SCL
I2C_SDA: R100.2 R102.2 ; port I2C_SDA
NRST_FTDI: R243.1 U27.45(CDBUS6)
RADAR_NRST_2: R243.2 ; port RADAR_NRST_2
RADAR_USER_LED_GPIO_6: R242.2 ; port RADAR_USER_LED_GPIO_6
REF_FTDI: R218.2 U27.6(REF)
RS232_FTDI_RX: R120.1 U27.48(DDBUS0)
RS232_FTDI_TX: R121.1 U27.52(DDBUS1)
RST_FTDI: R237.2 U27.14(RESET#)
SOP0_FTDI: R249.1 U27.55(DDBUS4)
SOP1_FTDI: R248.1 U27.54(DDBUS3)
VPHY_FTDI: C141.1 C142.2 L2.2 U27.4(VPHY)
VPLL_FTDI: C145.1 C146.2 L3.2 U27.9(VPLL)
XI_FTDI: C148.1 U27.2(OSCI) Y3.1
XO_FTDI: C147.1 U27.3(OSCO) Y3.3
NetC158_1: C158.1 R259.1 U29.6(VCC)
NetD10_2: D10.2(A) R252.2
NetR185_2: R185.2 U26.3(DI)
NetR242_1: R242.1 U27.59(DDBUS7)
NetR251_1: R251.1 U27.36(SUSPEND#)
NetR260_2: R260.2 U29.5(IO4)

Not connected (* = marked no-connect by the designer): U26 6(NC)* 7(NC)*; U27 21(ADBUS4)* 22(ADBUS5)* 23(ADBUS6)* 24(ADBUS7)* 29(BDBUS3)* 30(BDBUS4)* 33(BDBUS6)* 40(CDBUS2)* 41(CDBUS3)* 43(CDBUS4)* 44(CDBUS5)* 46(CDBUS7)* 53(DDBUS2)* 57(DDBUS5)* 58(DDBUS6)* 60(PWREN#)*

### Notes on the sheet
- FTDI - USB to SPI CONVERTER
- Review Note
- VCORE DECAPS
- 12MHz XTAL
- VREGOUT DECAPS
- FTDI USB PORT
- VREGIN DECAPS
- VCCIO DECAPS
- FTDI USB - ESD PROTECTION

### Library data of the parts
C138 C140 C142-C144 C146 C150 C152 C153 C158 = CMP-0006356-2: as C107 on sheet PROC182A_MUX_CAN_FD
C139 C141 C145 = CMP-0007058-4: CAP, CERM, 4.7 uF, 10 V, +/- 10%, X7S, 0603; Manufacturer: TDK; TaMin_C: -55°C; Polarized: N; SizeAreaWB_mm2: 4.68; Value1: Unknown; U/M: EA; Value: 4.7uF; TaMax_C: 125°C; SizeZ_mm: 1; SizeX_mm: 1.6; SizeY_mm: 0.8; Cap_Case: 0603; Value2: 10V; SizeArea_mm2: 1.28; CompType: Capacitor; Cap_F: 4.7µF; AEC Category: Q200
C147 C148 = CMP-0087060-3: Cap Ceramic 8pF 50V C0G 0.5pF SMD 0402 125C Paper T/R; Manufacturer: Murata Electronics North America; AEC Qualified: Yes; TempCo: 30ppm/°C; AEC Grade: Grade 1; SizeZ_mm: 0.55mm
C149 C151 = CMP-0086540-3: CAP, 1uF, 25V, ±10%, X7R, 0603; Manufacturer: Samsung; TempCo: 15%; SizeZ_mm: 0.9mm; AEC Qualified: No; Cap_F: 1µF; Symbol Name: SYM-CL10B105KA8NNNC
C157 = CMP-0007497-5: CAP, CERM, 10 uF, 10 V, +/- 10%, X5R, 0603; Manufacturer: MuRata; Polarized: N; Value: 10uF; U/M: EA; Cap_F: 10µF; Tolerance_%: 20%; Value1: Unknown; VDC_V: 10V; TempCo: X7R; TaMin_C: -55°C; TaMax_C: 125°C; Cap_Case: 0603; SizeArea_mm2: 1.28; SizeAreaWB_mm2: 4.68; SizeX_mm: 1.6; SizeY_mm: 0.8; SizeZ_mm: 1; AEC Category: Q200
D10 = CMP-0121062-1: Yellow 589nm LED Indication - Discrete 2.1V 0603 (1608 Metric); Manufacturer: Vishay; Angle: 160°; LambdaP: 591nm; Power_TotalModule: 90mW; SizeZ_mm: 0.65mm; Tjmax_C: 120°C; Vr_V: 12V; AEC Grade: Grade 3; AEC Qualified: Yes; Forward Current: 20mA; Led Orientation: Top View; Luminous Intensity: 80mcd; TaMax_C: +100°C; TaMin_C: -40°C
J10 = CMP-0055293-1: Connector, Receptacle, Micro-USB Type B, R/A, Bottom Mount SMT; Manufacturer: Molex; CNHeader: FALSE; Green_Lifecycle: Active; Gender: Female; Green_REACh: Passed; CompType: USB; CT: TRUE
L2 L3 L7 = CMP-0081523-1: Ferrite Bead, 600 ohm @ 100 MHz, 0.3 A, 0402; Manufacturer: MuRata; SizeAreaWB_mm2: 3; SizeArea_mm2: 0.5; Value: 600 ohm; SizeZ_mm: 0.6; Imax_A: 3dA; ZTyp@100MHz_Ohm: 600; Value2: 0.3A; Value1: 0.7 ohm; DCR_ohm: 7d; SizeX_mm: 1; Ztyp@1GHz_Ohm: 1k
R96 R100 R102 R118 R120 R121 R189 R216 R217 R242 R243 R259 = CMP-0002710-1: as R129 on sheet PROC182A_MUX_CAN_FD
R99 = CMP-0025950-3: as R147 on sheet PROC182A_MUX_CAN_FD
R119 = CMP-0002710-1: 0 Ohms Jumper Chip Resistor 0402 (1005 Metric) Automotive AEC-Q200 Thick Film; Manufacturer: Panasonic; Value: 0; SizeZ_mm: 0.4mm; AEC Qualified: Yes; AEC Grade: Grade 0; Power: 100mW
R167 R168 R184 R218 = CMP-0025958-3: as R127 on sheet PROC182A_MUX_CAN_FD
R185 = CMP-0026890-5: RES, 2.2 k, 5%, 0.063 W, AEC-Q200 Grade 0, 0402; Manufacturer: Vishay-Dale; Power_W: 63mW; TempCo: 200 ppm/C; Value_Code: 2k20; Value: 2.2k; EIA_Code: E24; SizeX_mm: 1; SizeY_mm: 0.5; SizeZ_mm: 0.6; Value2: 0.063W; AEC Qualified: Y; VDC_V: 50V; AEC Category: Q200; AEC Grade: 0
R186 R187 R209 R248 R249 R251 = CMP-0026299-2: RES, 33.2, 1%, 0.063 W, AEC-Q200 Grade 0, 0402; Manufacturer: Vishay-Dale; Power_W: 63mW; TempCo: 100 ppm/C; Value_Code: 33R2; Value: 33.2; EIA_Code: E96; SizeX_mm: 1; SizeY_mm: 0.5; SizeZ_mm: 0.6; Value2: 0.063W; AEC Qualified: Y; VDC_V: 50V; AEC Category: Q200; AEC Grade: 0
R237 = CMP-0026657-1: as R21 on sheet PROC182A_CAN_LIN_PHY_Interface
R252 = CMP-0078212-1: RES, 510, 5%, 0.1 W, AEC-Q200 Grade 0, 0402; Manufacturer: Panasonic; Value_Code: 510R; SizeArea_mm2: 0.5; AEC Qualified: Y; AEC Category: Q200; Value: 510; SizeZ_mm: 0.6; EIA_Code: E24; TempCo: 200 ppm/C; AEC Grade: 0; Power_W: 100mW; VDC_V: 50V; Value2: 0.1W; U/M: EA; SizeX_mm: 1
R260 = CMP-0078244-2: RES, 30.0 k, 1%, 0.063 W, AEC-Q200 Grade 0, 0402; Manufacturer: Vishay-Dale; Power_W: 63mW; Green_Lifecycle: Active; TempCo: 100 ppm/C; Value_Code: 30k0; Green_REACh: Passed; Value: 30.0k; Res_ohm: 30k; SizeX_mm: 1; SizeY_mm: 0.5; SizeZ_mm: 0.6; Value2: 0.063W; AEC Qualified: Y; VDC_V: 50V; AEC Grade: 0; AEC Category: Q200
U26 = CMP-0081524-1: 1K Microwire Compatible Serial EEPROM, TSSOP-8; Manufacturer: Microchip; SizeArea_mm2: 19.2; SizeAreaWB_mm2: 42; SizeY_mm: 3; SizeZ_mm: 1.2; SizeX_mm: 6.4
U27 = CMP-0004747-1: Quad High Speed USB to Multipurpose UART/MPSSE IC; Manufacturer: FTDI
U29 = CMP-0043115-3: 4-Channel ESD Protection Array for High-Speed Data Interfaces, DRY0006A (USON-6); Manufacturer: Texas Instruments; IO Leakage Current(nA): 1; USB High Speed: TRUE; IO Capacitance(Typ)(pF): 1.6; Eco-Plan: Green (RoHS & no Sb/Br); IEC 61000-4-2 Contact(+/- kV): 8; Breakdown Voltage(Min)(V): 6; IEC 61000-4-2 Air-Gap(+/- kV): 12; AEC Category: Q200; AEC Qualified: N; CompType: IC; SizeAreaWB_mm2: 4.9; SizeArea_mm2: 1.45; SizeX_mm: 1.0; SizeZ_mm: 0.6; Rating: Catalog
Y3 = CMP-0081529-1: Crystal, 12 MHz, 15 ppm, 8 pF, AEC-Q200 Grade 1, SMD; Manufacturer: NDK; TaMin_C: -40°C; Frequency Tolerance: 15 ppm; Frequency Stability: 50 ppm; Load Capacitance: 8 pF; Frequency_Fixed: 12MHz; TaMax_C: 125°C; AEC Qualified: Y; AEC Grade: 1; AEC Category: Q200

## Sheet PROC182A_DCA1000_Connector_Reset.SchDoc: DCA1000_CONN_RESET
size 431 x 279 mm; Date: Not shown in title block; ApprovedBy: Not shown in title block; CheckedBy: Not shown in title block; Author: Not shown in title block; CompanyName: Not shown in title block; DrawnBy: Mistral; Engineer: Not shown in title block; Organization: Not shown in title block; Address1: Not shown in title block; Address2: Not shown in title block; Address3: Not shown in title block; Address4: Not shown in title block; DocumentNumber: 15; Revision: Use project parameter SCH_Rev; SheetNumber: 15; SheetTotal: 17; PageSetup: Record=PageOptions¦CenterHorizontal=True¦CenterVertical=True¦PrintScale=1.00¦XCorrection=1.00¦YCorrection=1.00¦PrintKind=0¦BorderSize=5000000¦LeftOffset=0¦BottomOffset=0¦Orientation=2¦PaperLength=1000¦PaperWidth=1000¦Scale=100¦PaperSource=15¦PrintQuality=600¦MediaType=1¦DitherType=10¦PaperKind=Letter¦PrintScaleMode=1
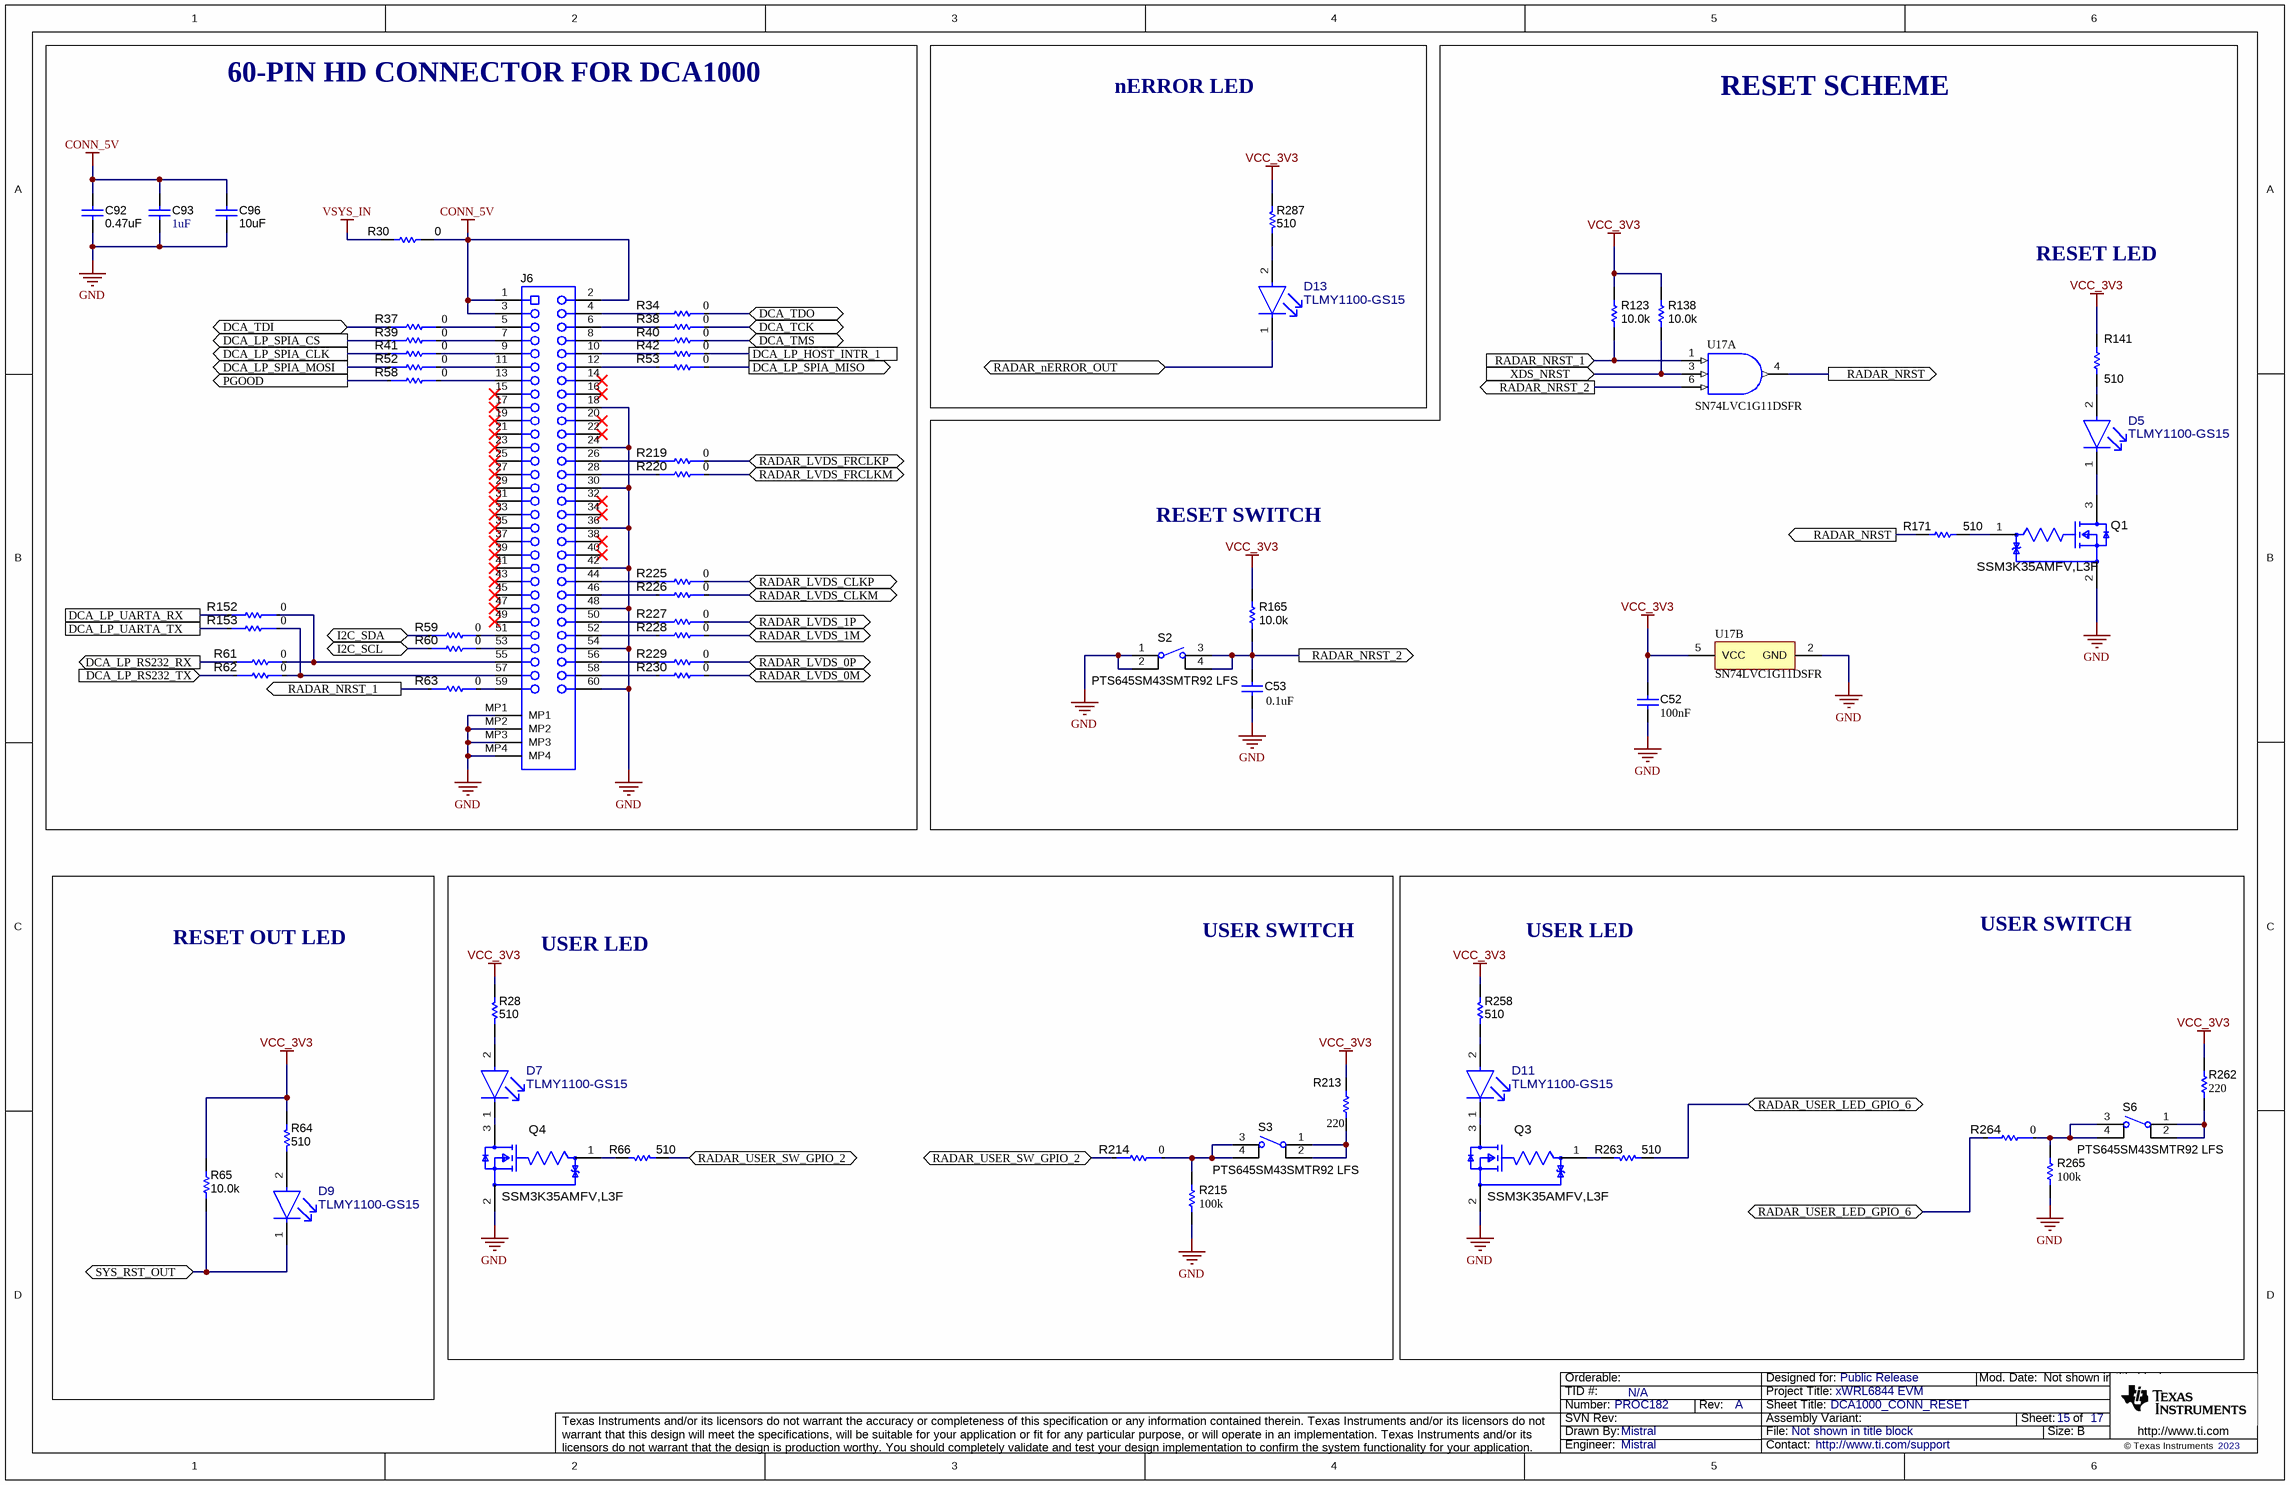
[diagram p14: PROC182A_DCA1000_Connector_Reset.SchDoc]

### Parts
C52  Cap_F: 100nF  [0402]  (hidden comment: GCM155R71H104KE02D)
C53  ValueDisplayed: 0.1uF  [0402]  (hidden comment: GCM155R71H104KE02D)
C92  ValueDisplayed: 0.47uF  [0402L]  (hidden comment: GCM155C71A474KE36D)
C93  ValueDisplayed: 1uF  [0402_070]  (hidden comment: GCM155C71A105KE38D)
C96  ValueDisplayed: 10uF  [0603S]  (hidden comment: GRT188R61A106KE13D)
D5  TLMY1100-GS15  [FP-TLMY1100-GS15_0603-MFG]
D7  TLMY1100-GS15  [FP-TLMY1100-GS15_0603-MFG]
D9  TLMY1100-GS15  [FP-TLMY1100-GS15_0603-MFG]
D11  TLMY1100-GS15  [FP-TLMY1100-GS15_0603-MFG]
D13  TLMY1100-GS15  [FP-TLMY1100-GS15_0603-MFG]
J6  QSH-030-01-L-D-A  [Samtec_QSH-030-01-X-D-A]  (value not drawn)
Q1  SSM3K35AMFV,L3F  [FP-SSM3K35AMFV,L3F_SOT-723-MFG]
Q3  SSM3K35AMFV,L3F  [FP-SSM3K35AMFV,L3F_SOT-723-MFG]
Q4  SSM3K35AMFV,L3F  [FP-SSM3K35AMFV,L3F_SOT-723-MFG]
R28  ValueDisplayed: 510  [0402L]  (hidden comment: ERJ-2GEJ511X)
R30  ValueDisplayed: 0  [0603]  (hidden comment: MCT06030Z0000ZP500)
R34  value 0  [FP-ERJ-2GE0R00X_0402-MFG]  (hidden comment: ERJ-2GE0R00X)
R37  value 0  [FP-ERJ-2GE0R00X_0402-MFG]  (hidden comment: ERJ-2GE0R00X)
R38  value 0  [FP-ERJ-2GE0R00X_0402-MFG]  (hidden comment: ERJ-2GE0R00X)
R39  value 0  [FP-ERJ-2GE0R00X_0402-MFG]  (hidden comment: ERJ-2GE0R00X)
R40  value 0  [FP-ERJ-2GE0R00X_0402-MFG]  (hidden comment: ERJ-2GE0R00X)
R41  value 0  [FP-ERJ-2GE0R00X_0402-MFG]  (hidden comment: ERJ-2GE0R00X)
R42  value 0  [FP-ERJ-2GE0R00X_0402-MFG]  (hidden comment: ERJ-2GE0R00X)
R52  value 0  [FP-ERJ-2GE0R00X_0402-MFG]  (hidden comment: ERJ-2GE0R00X)
R53  value 0  [FP-ERJ-2GE0R00X_0402-MFG]  (hidden comment: ERJ-2GE0R00X)
R58  value 0  [FP-ERJ-2GE0R00X_0402-MFG]  (hidden comment: ERJ-2GE0R00X)
R59  value 0  [FP-ERJ-2GE0R00X_0402-MFG]  (hidden comment: ERJ-2GE0R00X)
R60  value 0  [FP-ERJ-2GE0R00X_0402-MFG]  (hidden comment: ERJ-2GE0R00X)
R61  value 0  [FP-ERJ-2GE0R00X_0402-MFG]  (hidden comment: ERJ-2GE0R00X)
R62  value 0  [FP-ERJ-2GE0R00X_0402-MFG]  (hidden comment: ERJ-2GE0R00X)
R63  value 0  [FP-ERJ-2GE0R00X_0402-MFG]  (hidden comment: ERJ-2GE0R00X)
R64  ValueDisplayed: 510  [0402L]  (hidden comment: ERJ-2GEJ511X)
R65  ValueDisplayed: 10.0k  [0402L]  (hidden comment: CRCW040210K0FKED)
R66  ValueDisplayed: 510  [0402L]  (hidden comment: ERJ-2GEJ511X)
R123  ValueDisplayed: 10.0k  [0402L]  (hidden comment: CRCW040210K0FKED)
R138  ValueDisplayed: 10.0k  [0402L]  (hidden comment: CRCW040210K0FKED)
R141  ValueDisplayed: 510  [0402L]  (hidden comment: ERJ-2GEJ511X)
R152  value 0  [FP-ERJ-2GE0R00X_0402-MFG]  (hidden comment: ERJ-2GE0R00X)
R153  value 0  [FP-ERJ-2GE0R00X_0402-MFG]  (hidden comment: ERJ-2GE0R00X)
R165  ValueDisplayed: 10.0k  [0402L]  (hidden comment: CRCW040210K0FKED)
R171  ValueDisplayed: 510  [0402L]  (hidden comment: ERJ-2GEJ511X)
R213  ValueDisplayed: 220  [0402]  (hidden comment: CRCW0402220RJNED)
R214  Res_ohm: 0  [FP-ERJ-2GE0R00X_0402-MFG]  (hidden comment: ERJ-2GE0R00X)
R215  value 100k  [0402]  (hidden comment: CRCW0402100KFKED)
R219  value 0  [FP-ERJ-2GE0R00X_0402-MFG]  (hidden comment: ERJ-2GE0R00X)
R220  value 0  [FP-ERJ-2GE0R00X_0402-MFG]  (hidden comment: ERJ-2GE0R00X)
R225  value 0  [FP-ERJ-2GE0R00X_0402-MFG]  (hidden comment: ERJ-2GE0R00X)
R226  value 0  [FP-ERJ-2GE0R00X_0402-MFG]  (hidden comment: ERJ-2GE0R00X)
R227  value 0  [FP-ERJ-2GE0R00X_0402-MFG]  (hidden comment: ERJ-2GE0R00X)
R228  value 0  [FP-ERJ-2GE0R00X_0402-MFG]  (hidden comment: ERJ-2GE0R00X)
R229  value 0  [FP-ERJ-2GE0R00X_0402-MFG]  (hidden comment: ERJ-2GE0R00X)
R230  value 0  [FP-ERJ-2GE0R00X_0402-MFG]  (hidden comment: ERJ-2GE0R00X)
R258  ValueDisplayed: 510  [0402L]  (hidden comment: ERJ-2GEJ511X)
R262  ValueDisplayed: 220  [0402]  (hidden comment: CRCW0402220RJNED)
R263  ValueDisplayed: 510  [0402L]  (hidden comment: ERJ-2GEJ511X)
R264  Res_ohm: 0  [FP-ERJ-2GE0R00X_0402-MFG]  (hidden comment: ERJ-2GE0R00X)
R265  value 100k  [0402]  (hidden comment: CRCW0402100KFKED)
R287  ValueDisplayed: 510  [0402L]  (hidden comment: ERJ-2GEJ511X)
S2  PTS645SM43SMTR92 LFS  [SW_PTS645SM43SMT]
S3  PTS645SM43SMTR92 LFS  [SW_PTS645SM43SMT]
S6  PTS645SM43SMTR92 LFS  [SW_PTS645SM43SMT]
U17  SN74LVC1G11DSFR  [DSF0006A]  (parts A,B of 2)

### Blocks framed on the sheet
60-PIN HD CONNECTOR FOR DCA1000: C92 C93 C96 J6 R30 R34 R37-R42 R52 R53 R58-R63 R152 R153 R219 R220 R225-R230
RESET SCHEME: C52 C53 D5 Q1 R123 R138 R141 R165 R171 S2 U17
nERROR LED: D13 R287
RESET OUT LED: D9 R64 R65

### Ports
DCA_LP_HOST_INTR_1, DCA_LP_RS232_RX (out), DCA_LP_RS232_TX (in), DCA_LP_SPIA_CLK (out), DCA_LP_SPIA_CS (out), DCA_LP_SPIA_MISO (out), DCA_LP_SPIA_MOSI (out), DCA_LP_UARTA_RX, DCA_LP_UARTA_TX, DCA_TCK (bidir), DCA_TDI (bidir), DCA_TDO (bidir), DCA_TMS (bidir), I2C_SCL (bidir), I2C_SDA (bidir), PGOOD (out), RADAR_LVDS_0M (bidir), RADAR_LVDS_0P (bidir), RADAR_LVDS_1M (bidir), RADAR_LVDS_1P (bidir), RADAR_LVDS_CLKM (bidir), RADAR_LVDS_CLKP (bidir), RADAR_LVDS_FRCLKM (bidir), RADAR_LVDS_FRCLKP (bidir), RADAR_nERROR_OUT (bidir), RADAR_NRST (out), RADAR_NRST_1 (in), RADAR_NRST_1 (out), RADAR_NRST_2 (out), RADAR_USER_LED_GPIO_6 (bidir), RADAR_USER_SW_GPIO_2 (bidir), SYS_RST_OUT (bidir), XDS_NRST (in)

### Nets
CONN_5V: C92.1 C93.1 C96.2 J6.1 J6.2 J6.3 R30.2
GND: C52.1 C53.2 C92.2 C93.2 C96.1 J6.18 J6.24 J6.30 J6.36 J6.42 J6.48 J6.54 J6.60 J6.MP1 J6.MP2 J6.MP3 J6.MP4 Q1.2(S) Q3.2(S) Q4.2(S) R215.2 R265.2 S2.1 S2.2 U17.2(GND)
VCC_3V3: C52.2 R28.2 R64.2 R65.1 R123.2 R138.2 R141.2 R165.2 R213.2 R258.2 R262.2 R287.2 U17.5(VCC)
VSYS_IN: R30.1
DCA_LP_HOST_INTR_1: R42.2 ; port DCA_LP_HOST_INTR_1
DCA_LP_RS232_RX: R61.1 ; port DCA_LP_RS232_RX
DCA_LP_RS232_TX: R62.1 ; port DCA_LP_RS232_TX
DCA_LP_SPIA_CLK: R41.1 ; port DCA_LP_SPIA_CLK
DCA_LP_SPIA_CS: R39.1 ; port DCA_LP_SPIA_CS
DCA_LP_SPIA_MISO: R53.2 ; port DCA_LP_SPIA_MISO
DCA_LP_SPIA_MOSI: R52.1 ; port DCA_LP_SPIA_MOSI
DCA_LP_UARTA_RX: R152.2 ; port DCA_LP_UARTA_RX
DCA_LP_UARTA_TX: R153.2 ; port DCA_LP_UARTA_TX
DCA_TCK: R38.2 ; port DCA_TCK
DCA_TDI: R37.1 ; port DCA_TDI
DCA_TDO: R34.2 ; port DCA_TDO
DCA_TMS: R40.2 ; port DCA_TMS
I2C_SCL: R60.1 ; port I2C_SCL
I2C_SDA: R59.1 ; port I2C_SDA
PGOOD: R58.1 ; port PGOOD
RADAR_LVDS_0M: R230.2 ; port RADAR_LVDS_0M
RADAR_LVDS_0P: R229.2 ; port RADAR_LVDS_0P
RADAR_LVDS_1M: R228.2 ; port RADAR_LVDS_1M
RADAR_LVDS_1P: R227.2 ; port RADAR_LVDS_1P
RADAR_LVDS_CLKM: R226.2 ; port RADAR_LVDS_CLKM
RADAR_LVDS_CLKP: R225.2 ; port RADAR_LVDS_CLKP
RADAR_LVDS_FRCLKM: R220.2 ; port RADAR_LVDS_FRCLKM
RADAR_LVDS_FRCLKP: R219.2 ; port RADAR_LVDS_FRCLKP
RADAR_nERROR_OUT: D13.1(C) ; port RADAR_nERROR_OUT
RADAR_NRST: R171.2 U17.4(Y) ; port RADAR_NRST
RADAR_NRST_1: R63.1 R123.1 U17.1(A) ; port RADAR_NRST_1
RADAR_NRST_2: C53.1 R165.1 S2.3 S2.4 U17.6(C) ; port RADAR_NRST_2
RADAR_USER_LED_GPIO_6: R263.2 R264.2 ; port RADAR_USER_LED_GPIO_6
RADAR_USER_SW_GPIO_2: R66.2 R214.2 ; port RADAR_USER_SW_GPIO_2
SYS_RST_OUT: D9.1(C) R65.2 ; port SYS_RST_OUT
XDS_NRST: R138.1 U17.3(B) ; port XDS_NRST
NetD5_1: D5.1(C) Q1.3(D)
NetD5_2: D5.2(A) R141.1
NetD7_1: D7.1(C) Q4.3(D)
NetD7_2: D7.2(A) R28.1
NetD9_2: D9.2(A) R64.1
NetD11_1: D11.1(C) Q3.3(D)
NetD11_2: D11.2(A) R258.1
NetD13_2: D13.2(A) R287.1
NetJ6_4: J6.4 R34.1
NetJ6_5: J6.5 R37.2
NetJ6_6: J6.6 R38.1
NetJ6_7: J6.7 R39.2
NetJ6_8: J6.8 R40.1
NetJ6_9: J6.9 R41.2
NetJ6_10: J6.10 R42.1
NetJ6_11: J6.11 R52.2
NetJ6_12: J6.12 R53.1
NetJ6_13: J6.13 R58.2
NetJ6_26: J6.26 R219.1
NetJ6_28: J6.28 R220.1
NetJ6_44: J6.44 R225.1
NetJ6_46: J6.46 R226.1
NetJ6_50: J6.50 R227.1
NetJ6_51: J6.51 R59.2
NetJ6_52: J6.52 R228.1
NetJ6_53: J6.53 R60.2
NetJ6_55: J6.55 R61.2 R152.1
NetJ6_56: J6.56 R229.1
NetJ6_57: J6.57 R62.2 R153.1
NetJ6_58: J6.58 R230.1
NetJ6_59: J6.59 R63.2
NetQ1_1: Q1.1(G) R171.1
NetQ3_1: Q3.1(G) R263.1
NetQ4_1: Q4.1(G) R66.1
NetR213_1: R213.1 S3.1 S3.2
NetR214_1: R214.1 R215.1 S3.3 S3.4
NetR262_1: R262.1 S6.1 S6.2
NetR264_1: R264.1 R265.1 S6.3 S6.4

Not connected (* = marked no-connect by the designer): J6 14* 15* 16* 17* 19* 20* 21* 22* 23* 25* 27* 29* 31* 32* 33* 34* 35* 37* 38* 39* 40* 41* 43* 45* 47* 49*

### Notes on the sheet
- RESET LED
- RESET SWITCH
- USER LED
- USER SWITCH

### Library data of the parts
C52 = CMP-0006356-2: CAP, CERM, 0.1 uF, 50 V, +/- 10%, X7R, AEC-Q200 Grade 1, 0402; Manufacturer: MuRata; AEC Qualified: Y; SizeZ_mm: 0.6; VDC_V: 50V; AEC Category: Q200; AEC Grade: 1; Polarized: N; SizeArea_mm2: 0.5; SizeAreaWB_mm2: 3; TaMax_C: 125°C; TaMin_C: -55°C; U/M: EA; Value1: Unknown; Value: 0.1uF
C53 = CMP-0006356-2: as C123 on sheet PROC182A_CAN_LIN_PHY_Interface
C92 = CMP-0064967-2: CAP, CERM, 0.47 uF, 10 V,+/- 10%, X7S, 0402; Manufacturer: MuRata; Polarized: N; Value: 0.47uF; U/M: EA; Cap_F: 470nF; Value1: Unknown; VDC_V: 10V; TaMin_C: -55°C; TaMax_C: 125°C; Cap_Case: 0402; SizeArea_mm2: 0.5; SizeAreaWB_mm2: 3; SizeX_mm: 1; SizeZ_mm: 0.6; AEC Category: Q200
C93 = CMP-0006349-2: CAP, CERM, 1 uF, 10 V, +/- 10%, X7S, AEC-Q200 Grade 1, 0402; Manufacturer: MuRata; Polarized: N; Value: 1uF; U/M: EA; Cap_F: 1µF; Value1: Unknown; VDC_V: 10V; TaMin_C: -55°C; TaMax_C: 125°C; Cap_Case: 0402; SizeArea_mm2: 0.5; SizeAreaWB_mm2: 3; SizeX_mm: 1; SizeZ_mm: 0.7; AEC Category: Q200; AEC Qualified: Y
C96 = CMP-0007497-5: as C157 on sheet PROC182A_FTDI
D5 D7 D9 D11 D13 = CMP-0121062-1: as D10 on sheet PROC182A_FTDI
J6 = CMP-0075524-1: Receptacle, 0.5 mm, 30x2, Gold, TH; Manufacturer: Samtec; Pitch_mm: 0.5; Gender: Female; Green_REACh: Passed; CT: False; Shrouded: N; RowSpacing_mm: 5.73; Green_Lifecycle: Active; Row_Count: 2
Q1 Q3 Q4 = CMP-0091833-1: N-Channel 20V 250mA (Ta) 500mW (Ta) Surface Mount VESM; Manufacturer: Toshiba; Threshold Vgs Min: 0.35V; QgTyp_nC: 0.34nC @ 4.5V; AEC Qualified: No; Rdson45_ohm: 0.75; TJmax_C: +150°C; Input Capacitace At Vds: 18pF @ 10V; SizeZ_mm: 0.55mm; Pulse Drain Current: 600mA; Threshold Vgs Max: 1V; Vgs_V: 10V; Typ Forward Diode Voltage: 0.8V; VdsMax_V: 1.2V; Power_W: 150mW; Number Of N Channels: 1; Turn Off Delay Time: 6.5ns; ChMode: False; Turn On Delay Time: 2ns
R28 R64 R66 R141 R171 R258 R263 R287 = CMP-0078212-1: as R252 on sheet PROC182A_FTDI
R30 = CMP-0025884-3: as R31 on sheet PROC182A_CAN_LIN_PHY_Interface
R34 R37-R42 R52 R53 R58-R63 R152 R153 R219 R220 R225-R230 = CMP-0002710-1: as R129 on sheet PROC182A_MUX_CAN_FD
R65 R123 R138 R165 = CMP-0025958-3: as R127 on sheet PROC182A_MUX_CAN_FD
R213 R262 = CMP-0026878-3: RES, 220, 5%, 0.063 W, AEC-Q200 Grade 0, 0402; Manufacturer: Vishay-Dale; Power_W: 63mW; TempCo: 200 ppm/C; Value_Code: 220R; Value: 220; EIA_Code: E24; SizeX_mm: 1; SizeY_mm: 0.5; SizeZ_mm: 0.6; Value2: 0.063W; AEC Qualified: Y; VDC_V: 50V; AEC Category: Q200; AEC Grade: 0
R214 R264 = CMP-0002710-1: 0 Ohms Jumper Chip Resistor 0402 (1005 Metric) Automotive AEC-Q200 Thick Film; Manufacturer: Panasonic; AEC Qualified: Yes; SizeZ_mm: 0.4mm; AEC Grade: Grade 0; Power: 100mW; Value: 0
R215 R265 = CMP-0025950-3: RES, 100 k, 1%, 0.063 W, AEC-Q200 Grade 0, 0402; Manufacturer: Vishay-Dale; AEC Category: Q200; AEC Grade: 0; AEC Qualified: Y; EIA_Code: E96; Power_W: 63mW; SizeArea_mm2: 0.5; SizeX_mm: 1; SizeZ_mm: 0.6; TempCo: 100 ppm/C; Value2: 0.063W; VDC_V: 50V
S2 S3 S6 = CMP-0079642-1: Switch, SPST-NO, Off-Mom, 0.05 A, 12 VDC, SMD; Manufacturer: C&K Components; SizeAreaWB_mm2: 88; SizeArea_mm2: 54; SizeZ_mm: 4.4; SizeY_mm: 6; VDC_V: 12V; CurrentRating_mA: 50A; PositionCount: 1; SizeX_mm: 9
U17 = CMP-0051215-4: Single 3-Input Positive-AND Gate, DSF0006A, LARGE T&R; Manufacturer: Texas Instruments; Output Type: CMOS; Bits(#): 1; Input Type: CMOS/TTL; Technology Family: LVC; Schmitt Trigger: No; VCC(Max)(V): 5.5; Gate Type: AND; Rating: Catalog; Output Drive (IOL/IOH)(Max)(mA): 32/-32; ICC @ Nom Voltage(Max)(mA): 0.01; VCC(Min)(V): 1.65; F @ Nom Voltage(Max)(Mhz): 150; Logic: True; Voltage(Nom)(V): 1.8,2.5,3.3,5; tpd @ Nom Voltage(Max)(ns): 20,7.8,6.2,4.6

## Sheet PROC182A_I2C_SPI_Connector.SchDoc: I2C_SPI_UART_LP/BP_INTERFACE_CONN_HEADER
size 431 x 279 mm; Date: Not shown in title block; ApprovedBy: Not shown in title block; CheckedBy: Not shown in title block; Author: Not shown in title block; CompanyName: Not shown in title block; DrawnBy: Mistral; Engineer: Not shown in title block; Organization: Not shown in title block; Address1: Not shown in title block; Address2: Not shown in title block; Address3: Not shown in title block; Address4: Not shown in title block; DocumentNumber: 16; Revision: Use project parameter SCH_Rev; SheetNumber: 16; SheetTotal: 17; PageSetup: Record=PageOptions¦CenterHorizontal=True¦CenterVertical=True¦PrintScale=1.00¦XCorrection=1.00¦YCorrection=1.00¦PrintKind=0¦BorderSize=5000000¦LeftOffset=0¦BottomOffset=0¦Orientation=2¦PaperLength=1000¦PaperWidth=1000¦Scale=100¦PaperSource=15¦PrintQuality=600¦MediaType=1¦DitherType=10¦PaperKind=Letter¦PrintScaleMode=1
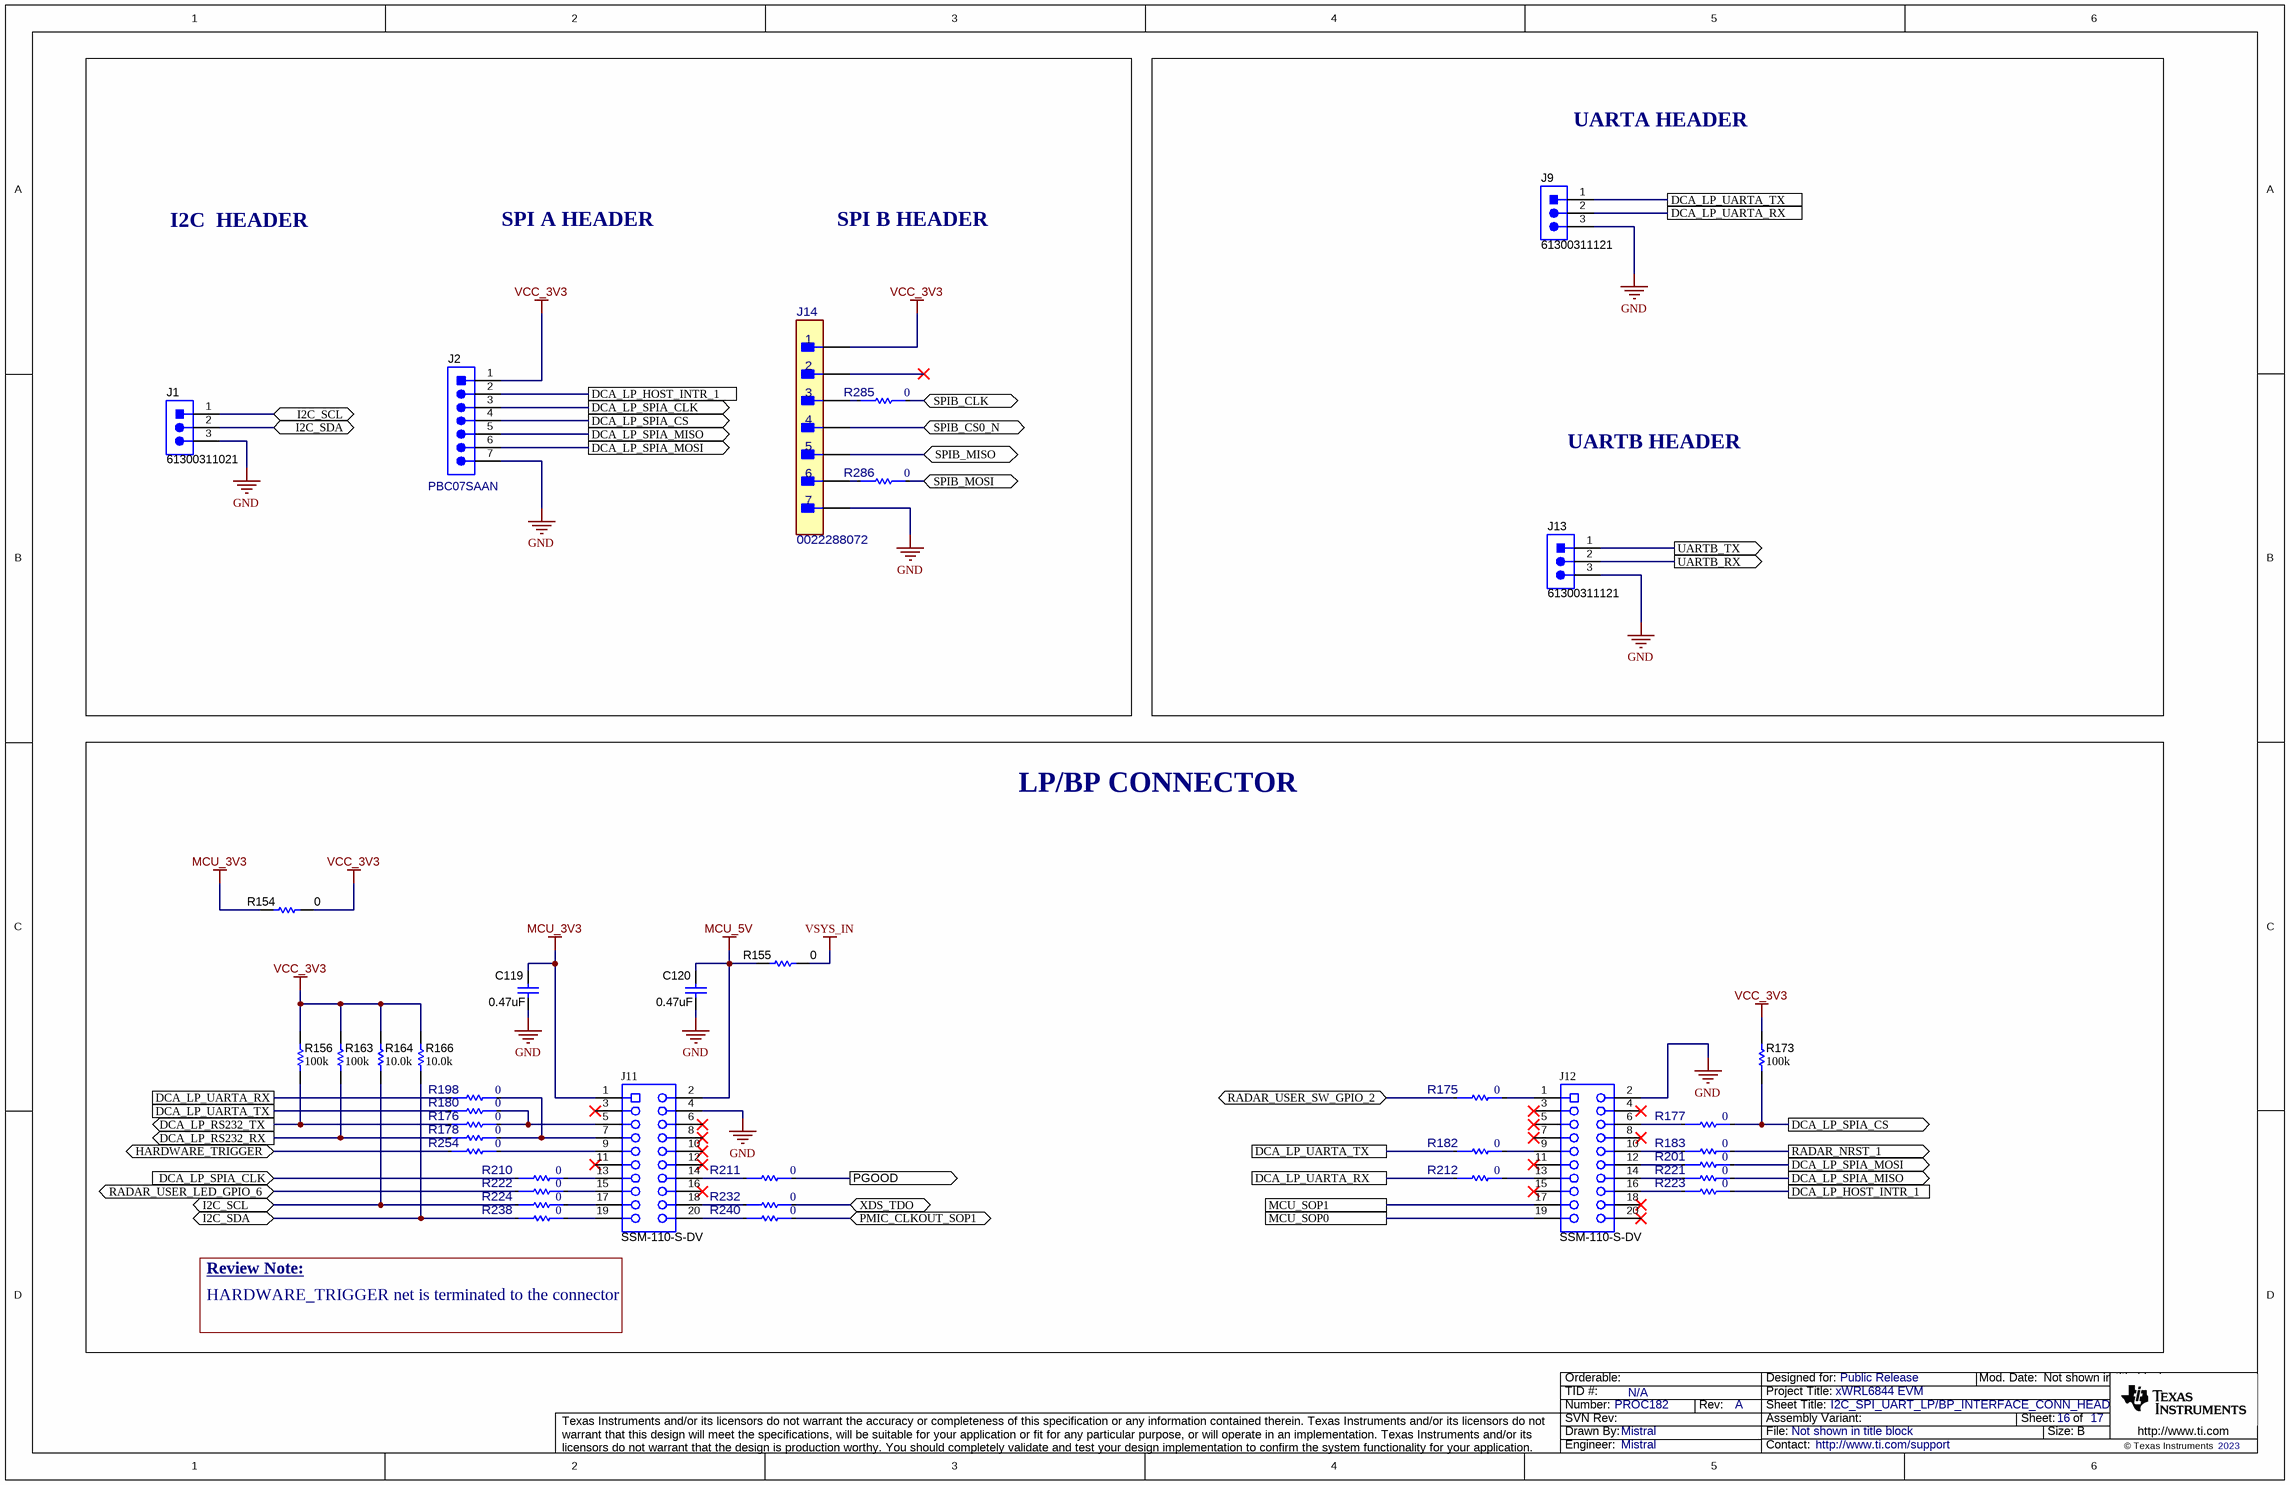
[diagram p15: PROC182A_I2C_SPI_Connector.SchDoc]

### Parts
C119  ValueDisplayed: 0.47uF  [0402L]  (hidden comment: GCM155C71A474KE36D)
C120  ValueDisplayed: 0.47uF  [0402L]  (hidden comment: GCM155C71A474KE36D)
J1  61300311021  [Wurth_61300311021]
J2  PBC07SAAN  [Sullins_xxC07SAAN]
J9  61300311121  [WURTH_61300311121]
J11  SSM-110-S-DV  [Samtec_SSM-110-x-DV]
J12  SSM-110-S-DV  [Samtec_SSM-110-x-DV]
J13  61300311121  [WURTH_61300311121]
J14  0022288072  [FP-0022288072_HDR7-MFG]
R154  ValueDisplayed: 0  [0603]  (hidden comment: MCT06030Z0000ZP500)
R155  ValueDisplayed: 0  [0603]  (hidden comment: MCT06030Z0000ZP500)
R156  ValueDisplayed: 100k  [0402L]  (hidden comment: CRCW0402100KFKED)
R163  ValueDisplayed: 100k  [0402L]  (hidden comment: CRCW0402100KFKED)
R164  ValueDisplayed: 10.0k  [0402L]  (hidden comment: CRCW040210K0FKED)
R166  ValueDisplayed: 10.0k  [0402L]  (hidden comment: CRCW040210K0FKED)
R173  ValueDisplayed: 100k  [0402L]  (hidden comment: CRCW0402100KFKED)
R175  value 0  [FP-ERJ-2GE0R00X_0402-MFG]  (hidden comment: ERJ-2GE0R00X)
R176  value 0  [FP-ERJ-2GE0R00X_0402-MFG]  (hidden comment: ERJ-2GE0R00X)
R177  value 0  [FP-ERJ-2GE0R00X_0402-MFG]  (hidden comment: ERJ-2GE0R00X)
R178  value 0  [FP-ERJ-2GE0R00X_0402-MFG]  (hidden comment: ERJ-2GE0R00X)
R180  value 0  [FP-ERJ-2GE0R00X_0402-MFG]  (hidden comment: ERJ-2GE0R00X)
R182  value 0  [FP-ERJ-2GE0R00X_0402-MFG]  (hidden comment: ERJ-2GE0R00X)
R183  value 0  [FP-ERJ-2GE0R00X_0402-MFG]  (hidden comment: ERJ-2GE0R00X)
R198  value 0  [FP-ERJ-2GE0R00X_0402-MFG]  (hidden comment: ERJ-2GE0R00X)
R201  value 0  [FP-ERJ-2GE0R00X_0402-MFG]  (hidden comment: ERJ-2GE0R00X)
R210  value 0  [FP-ERJ-2GE0R00X_0402-MFG]  (hidden comment: ERJ-2GE0R00X)
R211  value 0  [FP-ERJ-2GE0R00X_0402-MFG]  (hidden comment: ERJ-2GE0R00X)
R212  value 0  [FP-ERJ-2GE0R00X_0402-MFG]  (hidden comment: ERJ-2GE0R00X)
R221  value 0  [FP-ERJ-2GE0R00X_0402-MFG]  (hidden comment: ERJ-2GE0R00X)
R222  value 0  [FP-ERJ-2GE0R00X_0402-MFG]  (hidden comment: ERJ-2GE0R00X)
R223  value 0  [FP-ERJ-2GE0R00X_0402-MFG]  (hidden comment: ERJ-2GE0R00X)
R224  value 0  [FP-ERJ-2GE0R00X_0402-MFG]  (hidden comment: ERJ-2GE0R00X)
R232  value 0  [FP-ERJ-2GE0R00X_0402-MFG]  (hidden comment: ERJ-2GE0R00X)
R238  value 0  [FP-ERJ-2GE0R00X_0402-MFG]  (hidden comment: ERJ-2GE0R00X)
R240  value 0  [FP-ERJ-2GE0R00X_0402-MFG]  (hidden comment: ERJ-2GE0R00X)
R254  value 0  [FP-ERJ-2GE0R00X_0402-MFG]  (hidden comment: ERJ-2GE0R00X)
R285  value 0  [FP-ERJ-2GE0R00X_0402-MFG]  (hidden comment: ERJ-2GE0R00X)
R286  value 0  [FP-ERJ-2GE0R00X_0402-MFG]  (hidden comment: ERJ-2GE0R00X)

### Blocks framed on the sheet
LP/BP CONNECTOR: C119 C120 J11 J12 R154-R156 R163 R164 R166 R173 R175-R178 R180 R182 R183 R198 R201 R210-R212 R221-R224 R232 R238 R240 R254

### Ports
DCA_LP_HOST_INTR_1, DCA_LP_RS232_RX (out), DCA_LP_RS232_TX (out), DCA_LP_SPIA_CLK (in), DCA_LP_SPIA_CLK (out), DCA_LP_SPIA_CS (out), DCA_LP_SPIA_MISO (out), DCA_LP_SPIA_MOSI (out), DCA_LP_UARTA_RX, DCA_LP_UARTA_TX, HARDWARE_TRIGGER (bidir), I2C_SCL (bidir), I2C_SDA (bidir), MCU_SOP0, MCU_SOP1, PGOOD (out), PMIC_CLKOUT_SOP1 (bidir), RADAR_NRST_1 (out), RADAR_USER_LED_GPIO_6 (bidir), RADAR_USER_SW_GPIO_2 (bidir), SPIB_CLK (bidir), SPIB_CS0_N (bidir), SPIB_MISO (bidir), SPIB_MOSI (bidir), UARTB_RX (out), UARTB_TX (out), XDS_TDO (bidir)

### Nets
GND: C119.2 C120.2 J1.3 J2.7 J9.3 J11.4 J12.2 J13.3 J14.7
MCU_3V3: C119.1 J11.1 R154.1
MCU_5V: C120.1 J11.2 R155.1
VCC_3V3: J2.1 J14.1 R154.2 R156.2 R163.2 R164.2 R166.2 R173.2
VSYS_IN: R155.2
DCA_LP_HOST_INTR_1: J2.2 R223.2 ; port DCA_LP_HOST_INTR_1
DCA_LP_RS232_RX: R163.1 R178.1 ; port DCA_LP_RS232_RX
DCA_LP_RS232_TX: R156.1 R176.1 ; port DCA_LP_RS232_TX
DCA_LP_SPIA_CLK: J2.3 R210.1 ; port DCA_LP_SPIA_CLK
DCA_LP_SPIA_CS: J2.4 R173.1 R177.2 ; port DCA_LP_SPIA_CS
DCA_LP_SPIA_MISO: J2.5 R221.2 ; port DCA_LP_SPIA_MISO
DCA_LP_SPIA_MOSI: J2.6 R201.2 ; port DCA_LP_SPIA_MOSI
DCA_LP_UARTA_RX: J9.2 R198.1 R212.1 ; port DCA_LP_UARTA_RX
DCA_LP_UARTA_TX: J9.1 R180.1 R182.1 ; port DCA_LP_UARTA_TX
HARDWARE_TRIGGER: R254.1 ; port HARDWARE_TRIGGER
I2C_SCL: J1.1 R164.1 R224.1 ; port I2C_SCL
I2C_SDA: J1.2 R166.1 R238.1 ; port I2C_SDA
MCU_SOP0: J12.19 ; port MCU_SOP0
MCU_SOP1: J12.17 ; port MCU_SOP1
PGOOD: R211.2 ; port PGOOD
PMIC_CLKOUT_SOP1: R240.2 ; port PMIC_CLKOUT_SOP1
RADAR_NRST_1: R183.2 ; port RADAR_NRST_1
RADAR_USER_LED_GPIO_6: R222.1 ; port RADAR_USER_LED_GPIO_6
RADAR_USER_SW_GPIO_2: R175.1 ; port RADAR_USER_SW_GPIO_2
SPIB_CLK: R285.2 ; port SPIB_CLK
SPIB_CS0_N: J14.4 ; port SPIB_CS0_N
SPIB_MISO: J14.5 ; port SPIB_MISO
SPIB_MOSI: R286.2 ; port SPIB_MOSI
UARTB_RX: J13.2 ; port UARTB_RX
UARTB_TX: J13.1 ; port UARTB_TX
XDS_TDO: R232.2 ; port XDS_TDO
NetJ11_5: J11.5 R176.2 R180.2
NetJ11_7: J11.7 R178.2 R198.2
NetJ11_9: J11.9 R254.2
NetJ11_13: J11.13 R210.2
NetJ11_14: J11.14 R211.1
NetJ11_15: J11.15 R222.2
NetJ11_17: J11.17 R224.2
NetJ11_18: J11.18 R232.1
NetJ11_19: J11.19 R238.2
NetJ11_20: J11.20 R240.1
NetJ12_1: J12.1 R175.2
NetJ12_6: J12.6 R177.1
NetJ12_9: J12.9 R182.2
NetJ12_10: J12.10 R183.1
NetJ12_12: J12.12 R201.1
NetJ12_13: J12.13 R212.2
NetJ12_14: J12.14 R221.1
NetJ12_16: J12.16 R223.1
NetJ14_3: J14.3 R285.1
NetJ14_6: J14.6 R286.1

Not connected (* = marked no-connect by the designer): J11 3* 6* 8* 10* 11* 12* 16*; J12 3* 4* 5* 7* 8* 11* 15* 18* 20*; J14 2*

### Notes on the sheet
- UARTA HEADER
- I2C  HEADER
- SPI A HEADER
- SPI B HEADER
- UARTB HEADER
- Review Note:
- HARDWARE_TRIGGER net is terminated to the connector

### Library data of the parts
C119 C120 = CMP-0064967-2: as C92 on sheet PROC182A_DCA1000_Connector_Reset
J1 = CMP-0054795-1: as J8 on sheet PROC182A_MUX_CAN_FD
J2 = CMP-0054584-1: Header, 2.54 mm, 7x1, Gold, TH; Manufacturer: Sullins Connector Solutions; CNHeader: TRUE; Current_A: 3A; Shrouded: N; Gender: Male; Voltage_V: 1.8kV; Row_Count: 1; Pitch_mm: 2.54; CT: FALSE; Cert_UL: Y
J9 J13 = CMP-0054796-4: Header, 2.54 mm, 3x1, Gold, TH; Manufacturer: Wurth Elektronik; Green_REACh: Passed; CT: FALSE; CNHeader: TRUE; Green_Lifecycle: Active
J11 J12 = CMP-0078182-1: Receptacle, 2.54mm, 10x2, Gold with Tin tail, SMT; Manufacturer: Samtec; Pitch_mm: 2.54; Gender: Female; Cert_CSA: Y; Voltage_V: 405V; Current_A: 5.2A; Row_Count: 2; CompType: Socket Strip
J14 = CMP-0120118-1: Manufacturer: Molex; ContactFinish: Gold,Nickel; Current_A: 4A; Row_Count: 1; Voltage_V: 600V; AEC Qualified: No; Conn Gender: Male; Conn Orientation: Right Angle; DUT-Pitch_mm: 2.54mm; SizeZ_mm: 2.74mm
R154 R155 = CMP-0025884-3: as R31 on sheet PROC182A_CAN_LIN_PHY_Interface
R156 R163 R173 = CMP-0025950-3: as R147 on sheet PROC182A_MUX_CAN_FD
R164 R166 = CMP-0025958-3: as R127 on sheet PROC182A_MUX_CAN_FD
R175-R178 R180 R182 R183 R198 R201 R210-R212 R221-R224 R232 R238 R240 R254 R285 R286 = CMP-0002710-1: as R129 on sheet PROC182A_MUX_CAN_FD

## Sheet PROC182A_EVM_Hardware.SchDoc: HARDWARE
size 431 x 279 mm; Date: Not shown in title block; ApprovedBy: Not shown in title block; CheckedBy: Not shown in title block; Author: Not shown in title block; CompanyName: Not shown in title block; DrawnBy: Mistral; Engineer: Not shown in title block; Organization: Not shown in title block; Address1: Not shown in title block; Address2: Not shown in title block; Address3: Not shown in title block; Address4: Not shown in title block; DocumentNumber: 16; Revision: Use project parameter SCH_Rev; SheetNumber: 17; SheetTotal: 17; PageSetup: Record=PageOptions¦CenterHorizontal=True¦CenterVertical=True¦PrintScale=1.00¦XCorrection=1.00¦YCorrection=1.00¦PrintKind=0¦BorderSize=5000000¦LeftOffset=0¦BottomOffset=0¦Orientation=2¦PaperLength=1000¦PaperWidth=1000¦Scale=100¦PaperSource=15¦PrintQuality=600¦MediaType=1¦DitherType=10¦PaperKind=Letter¦PrintScaleMode=1
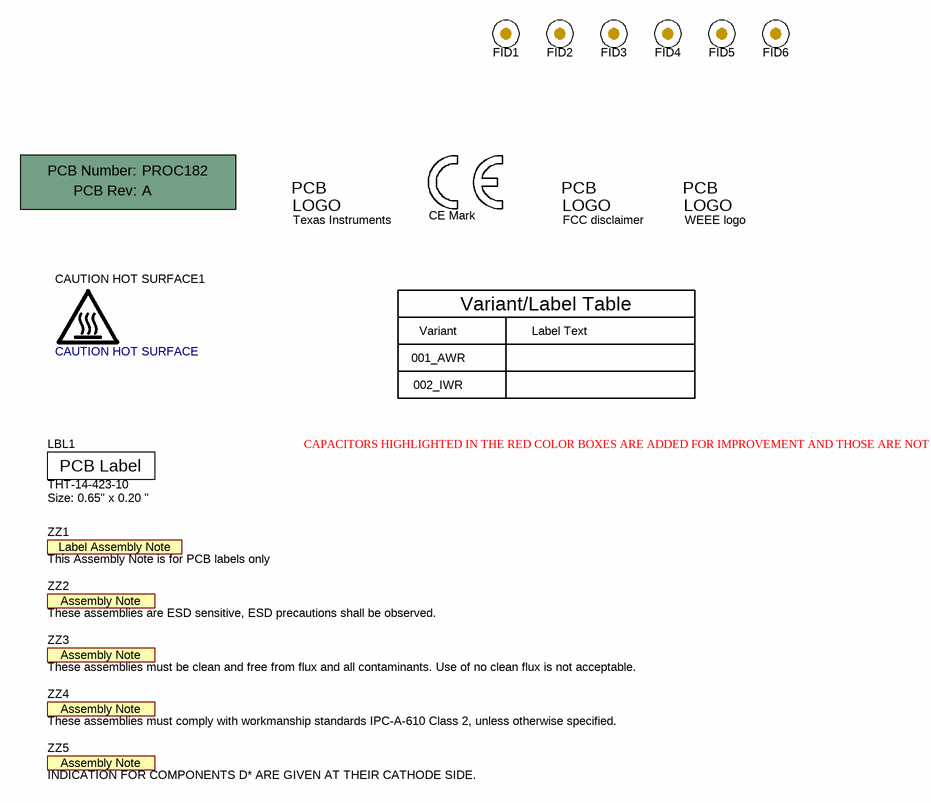
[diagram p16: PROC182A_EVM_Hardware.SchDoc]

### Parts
!PCB  Printed Circuit Board  (value not drawn)  (mechanical)
CAUTION_HOT_SURFACE1  CAUTION HOT SURFACE  [IEC_HotSurface_Small]  (no BOM)
FID1  Fiducial  [Fiducial10-20]  (value not drawn)
FID2  Fiducial  [Fiducial10-20]  (value not drawn)
FID3  Fiducial  [Fiducial10-20]  (value not drawn)
FID4  Fiducial  [Fiducial10-20]  (value not drawn)
FID5  Fiducial  [Fiducial10-20]  (value not drawn)
FID6  Fiducial  [Fiducial10-20]  (value not drawn)
LBL1  THT-14-423-10  Note: Size: 0.65" x 0.20 "  [Label_650x200]
Logo1  Texas Instruments  [TI_Stacked_Overlay_Small]  (no BOM)
Logo2  CE Mark  [CE_Mark_5mm]  (no BOM)
Logo3  FCC disclaimer  [FCC_disclaimer]  (no BOM)
Logo4  WEEE logo  [WEEE_Minimum]  (no BOM)
ZZ1  This Assembly Note is for PCB labels only  [AssemblyNoteLabel]  (no BOM)
ZZ2  These assemblies are ESD sensitive, ESD precautions shall be observed.  [AssemblyNote]  (no BOM)
ZZ3  These assemblies must be clean and free from flux and all contaminants. Use of no clean flux is not acceptable.  [AssemblyNote]  (no BOM)
ZZ4  These assemblies must comply with workmanship standards IPC-A-610 Class 2, unless otherwise specified.  [AssemblyNote]  (no BOM)
ZZ5  INDICATION FOR COMPONENTS D* ARE GIVEN AT THEIR CATHODE SIDE.  [AssemblyNote]  (no BOM)

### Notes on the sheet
- Variant
- 001_AWR
- Variant/Label Table
- Label Text
- 002_IWR
- CAPACITORS HIGHLIGHTED IN THE RED COLOR BOXES ARE ADDED FOR IMPROVEMENT AND THOSE ARE NOT MANDITORY.

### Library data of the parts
!PCB = CMP-0003618-2: Manufacturer: Any; PartNumber: PROC182
CAUTION_HOT_SURFACE1 = CMP-0074837-2: IEC 61010-1 Hot Surface Warning; Manufacturer: Texas Instruments; SymbolCreator: a0412235; AEC Category: Q200; CompType: IC
FID1-FID6 = CMP-0077181-1: Fiducial mark.  There is nothing to buy or mount.
LBL1 = CMP-0003625-1: Thermal Transfer Printable Labels, 0.650" W x 0.200" H - 10,000 per roll; Manufacturer: Brady; CompType: Label
Logo1 = CMP-0074838-1: Texas Instrument Corporate Signature; SymbolCreator: a0412235; Lib Reference: TI_Logo; Library Reference: Logo
Logo2 = CMP-0074844-1: SymbolCreator: a0412235
Logo3 = CMP-0074847-1: FCC_disclaimer; Library Reference: Logo
Logo4 = CMP-0074769-1
ZZ1 = CMP-0003616-3
ZZ2 = CMP-0077236-1
ZZ3 = CMP-0077237-1
ZZ4 ZZ5 = CMP-0077238-1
